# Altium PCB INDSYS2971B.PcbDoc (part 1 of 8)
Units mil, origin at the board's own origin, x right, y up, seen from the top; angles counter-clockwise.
Board outline 6450 x 5820 mil, 6 copper layers (Top Layer, Int1 (PGND), Int2 (AGND), Int3 (Signal), Int4 (PGND), Bottom Layer), stack 70.536 mil thick; 787 components, 431 nets, 2530 pads, 2497 vias.
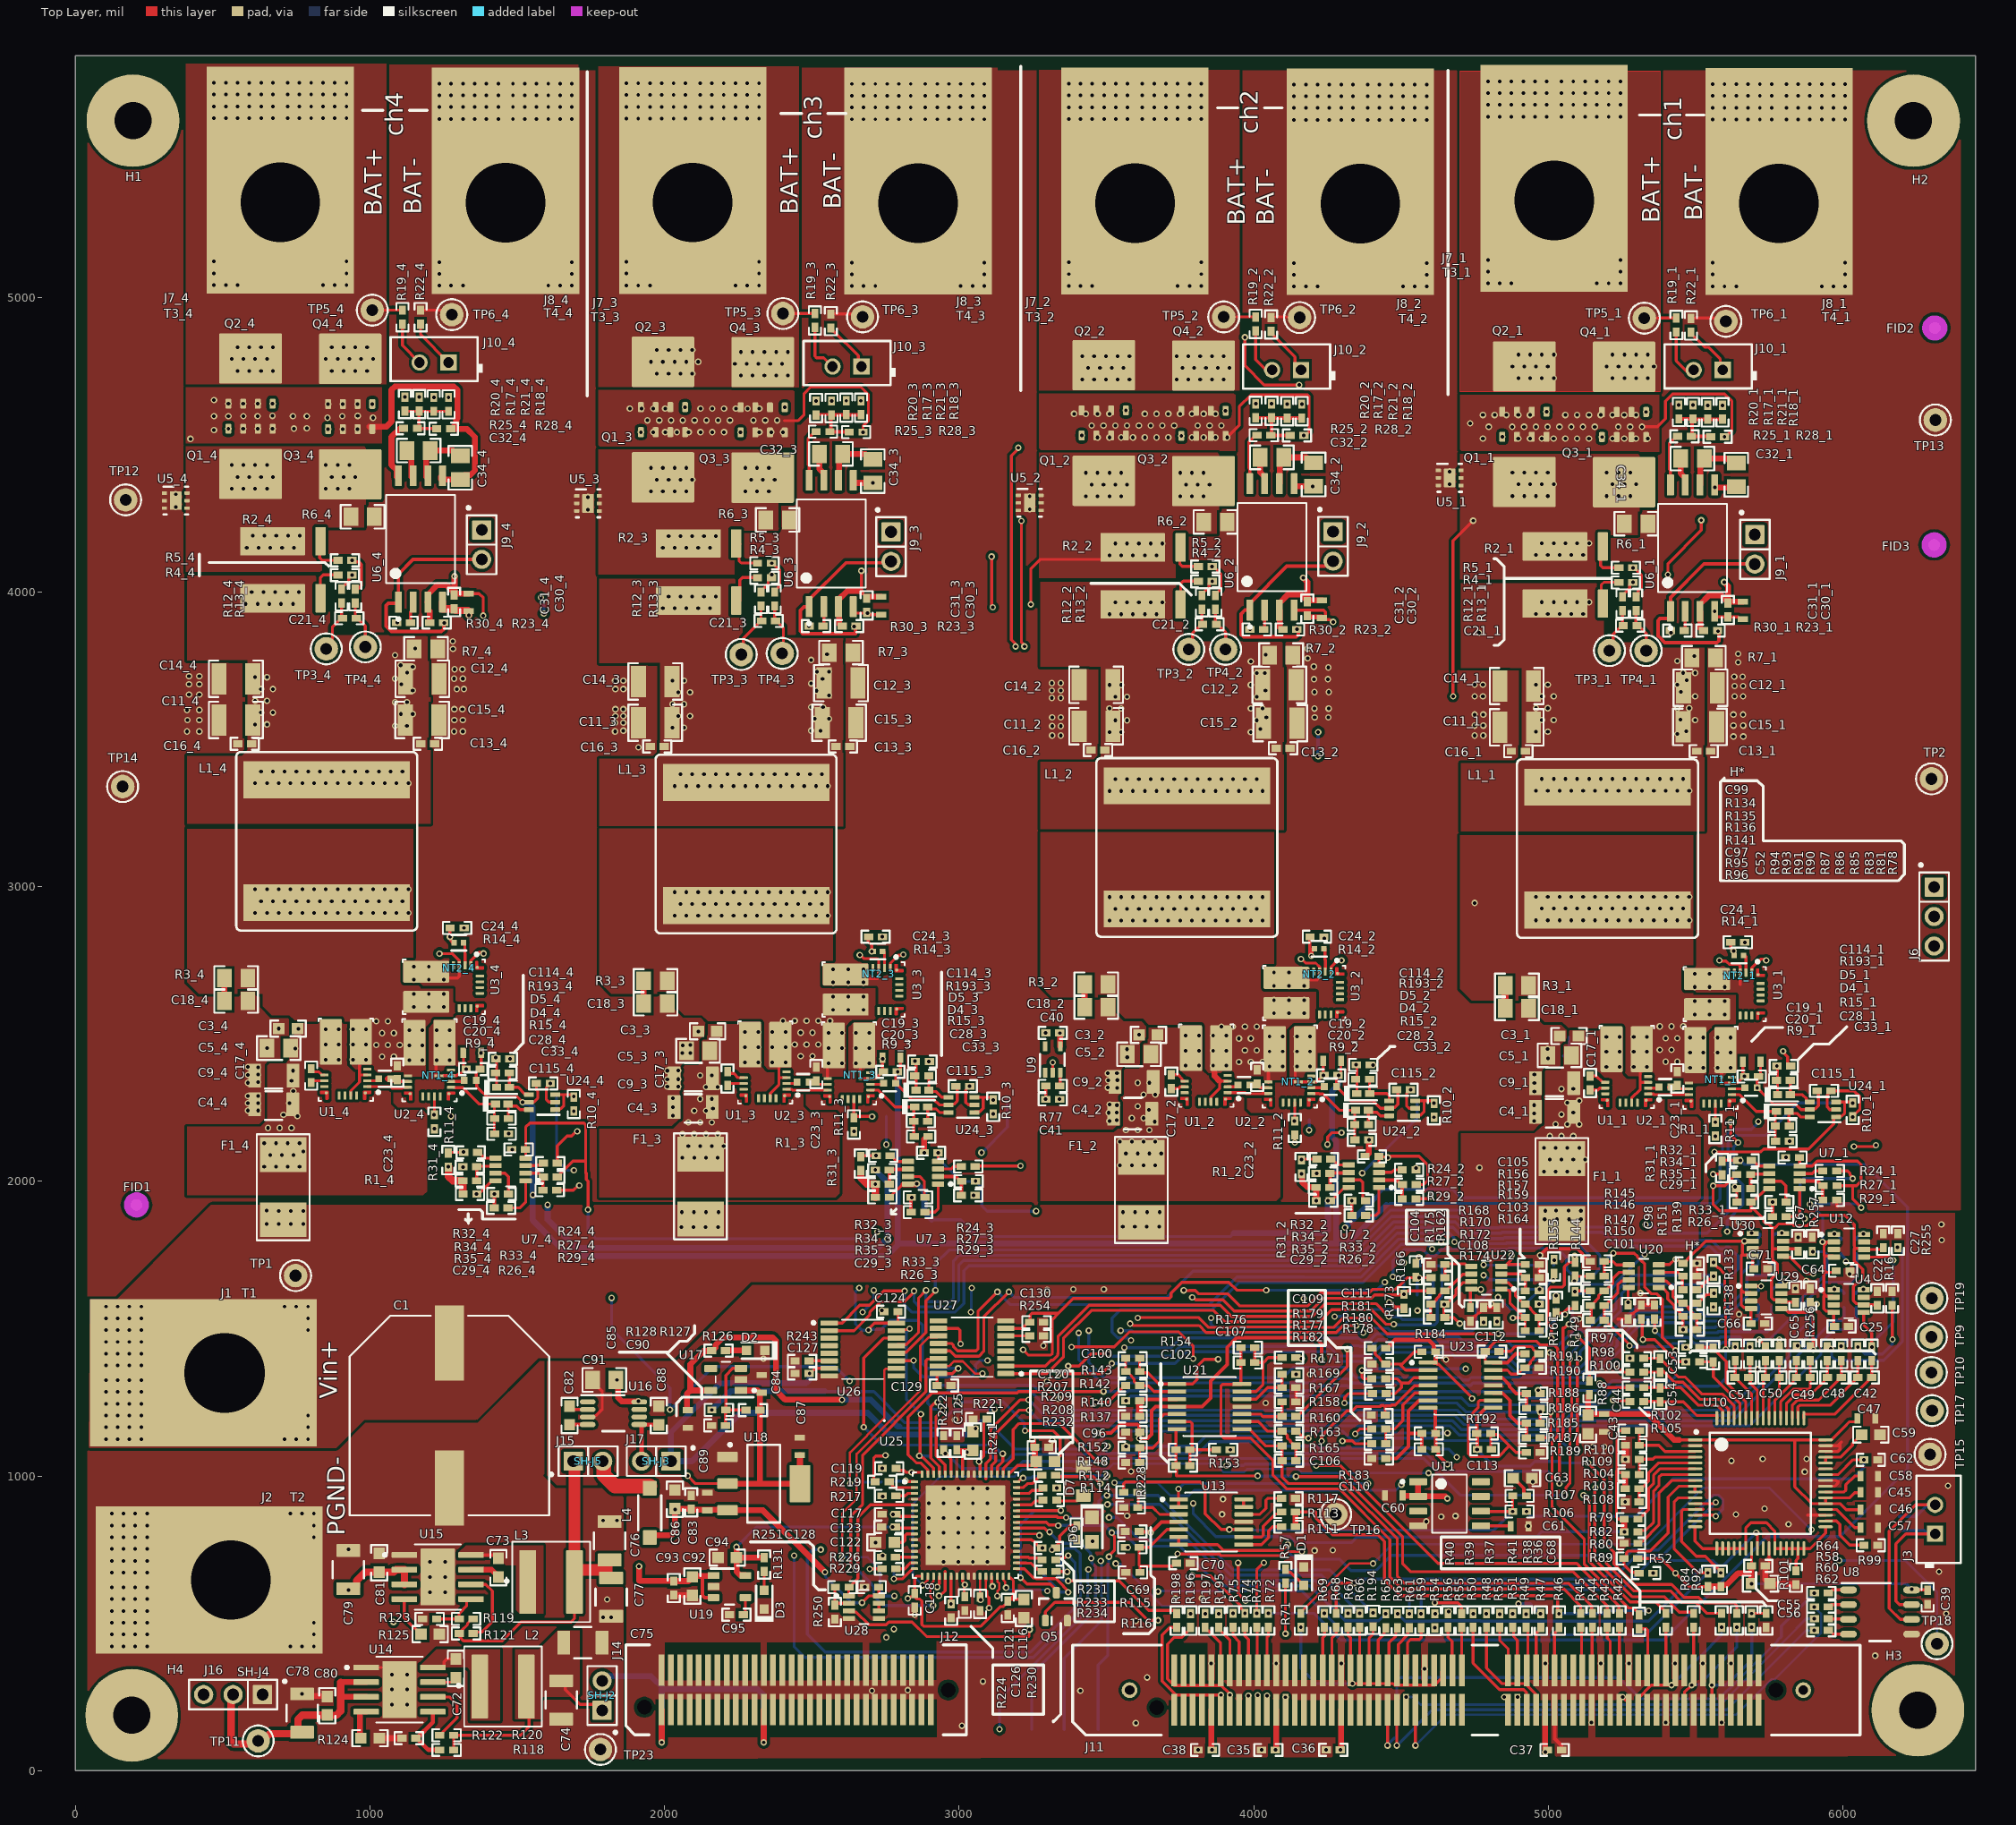
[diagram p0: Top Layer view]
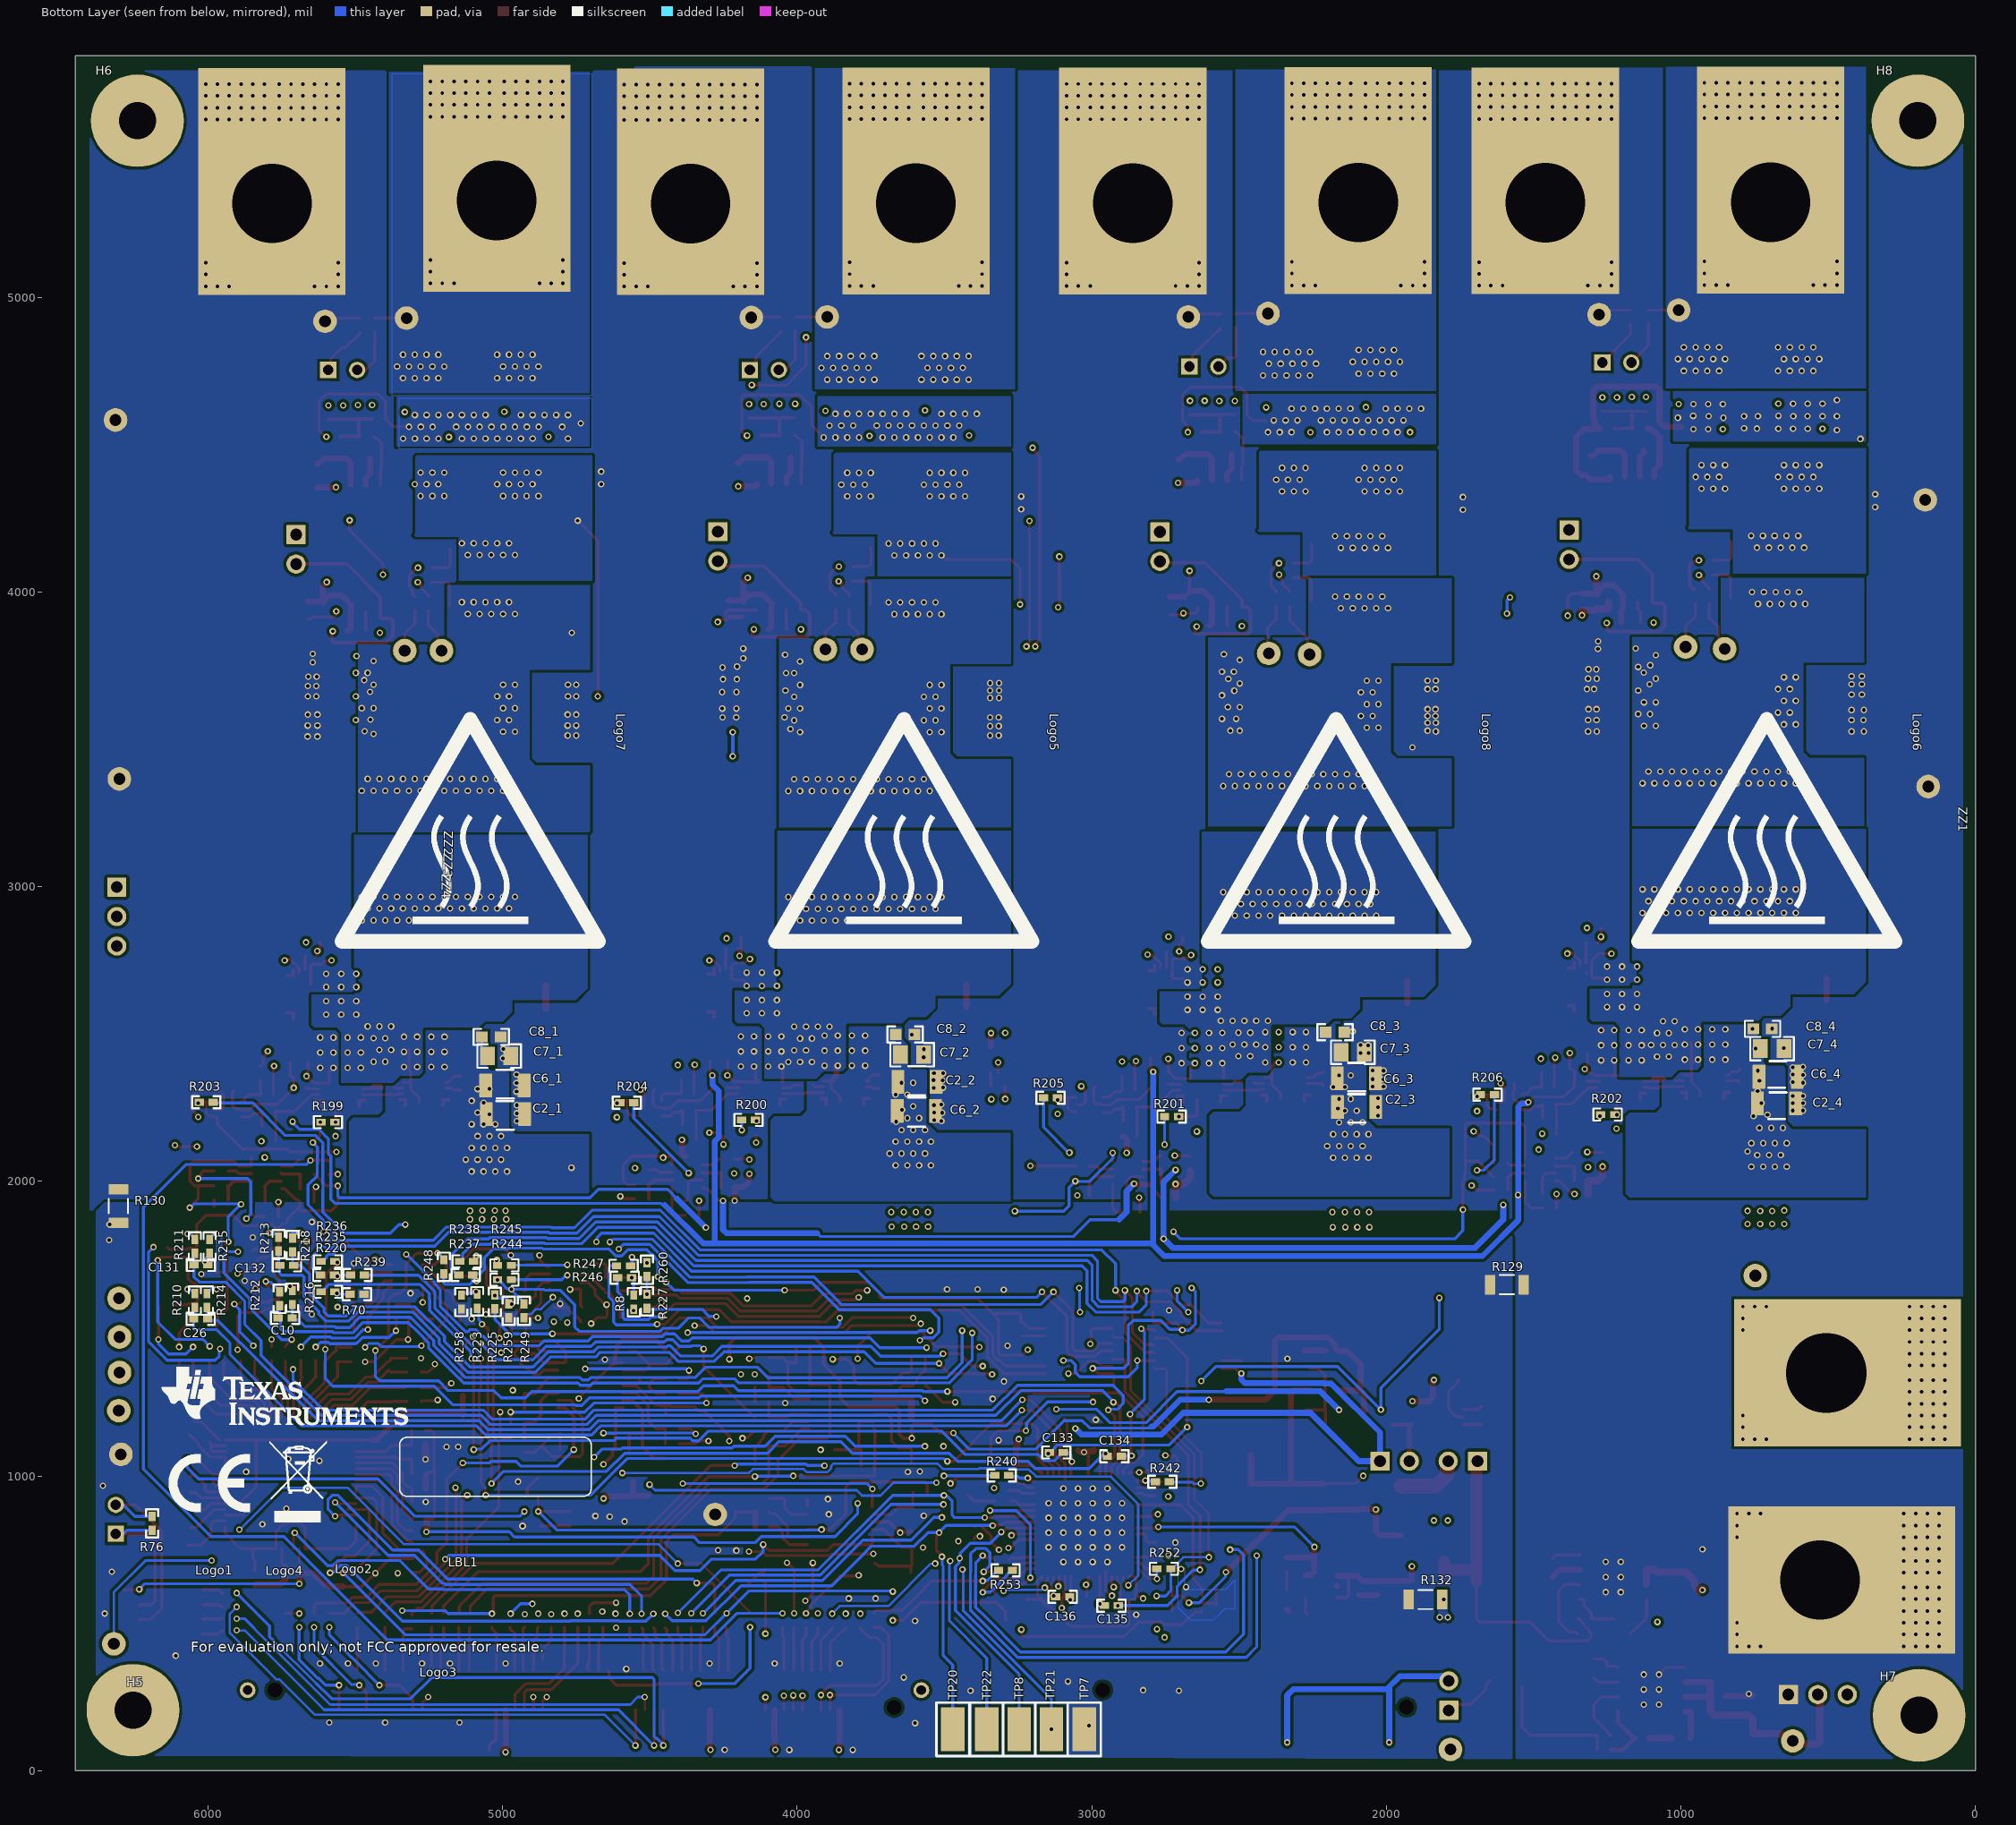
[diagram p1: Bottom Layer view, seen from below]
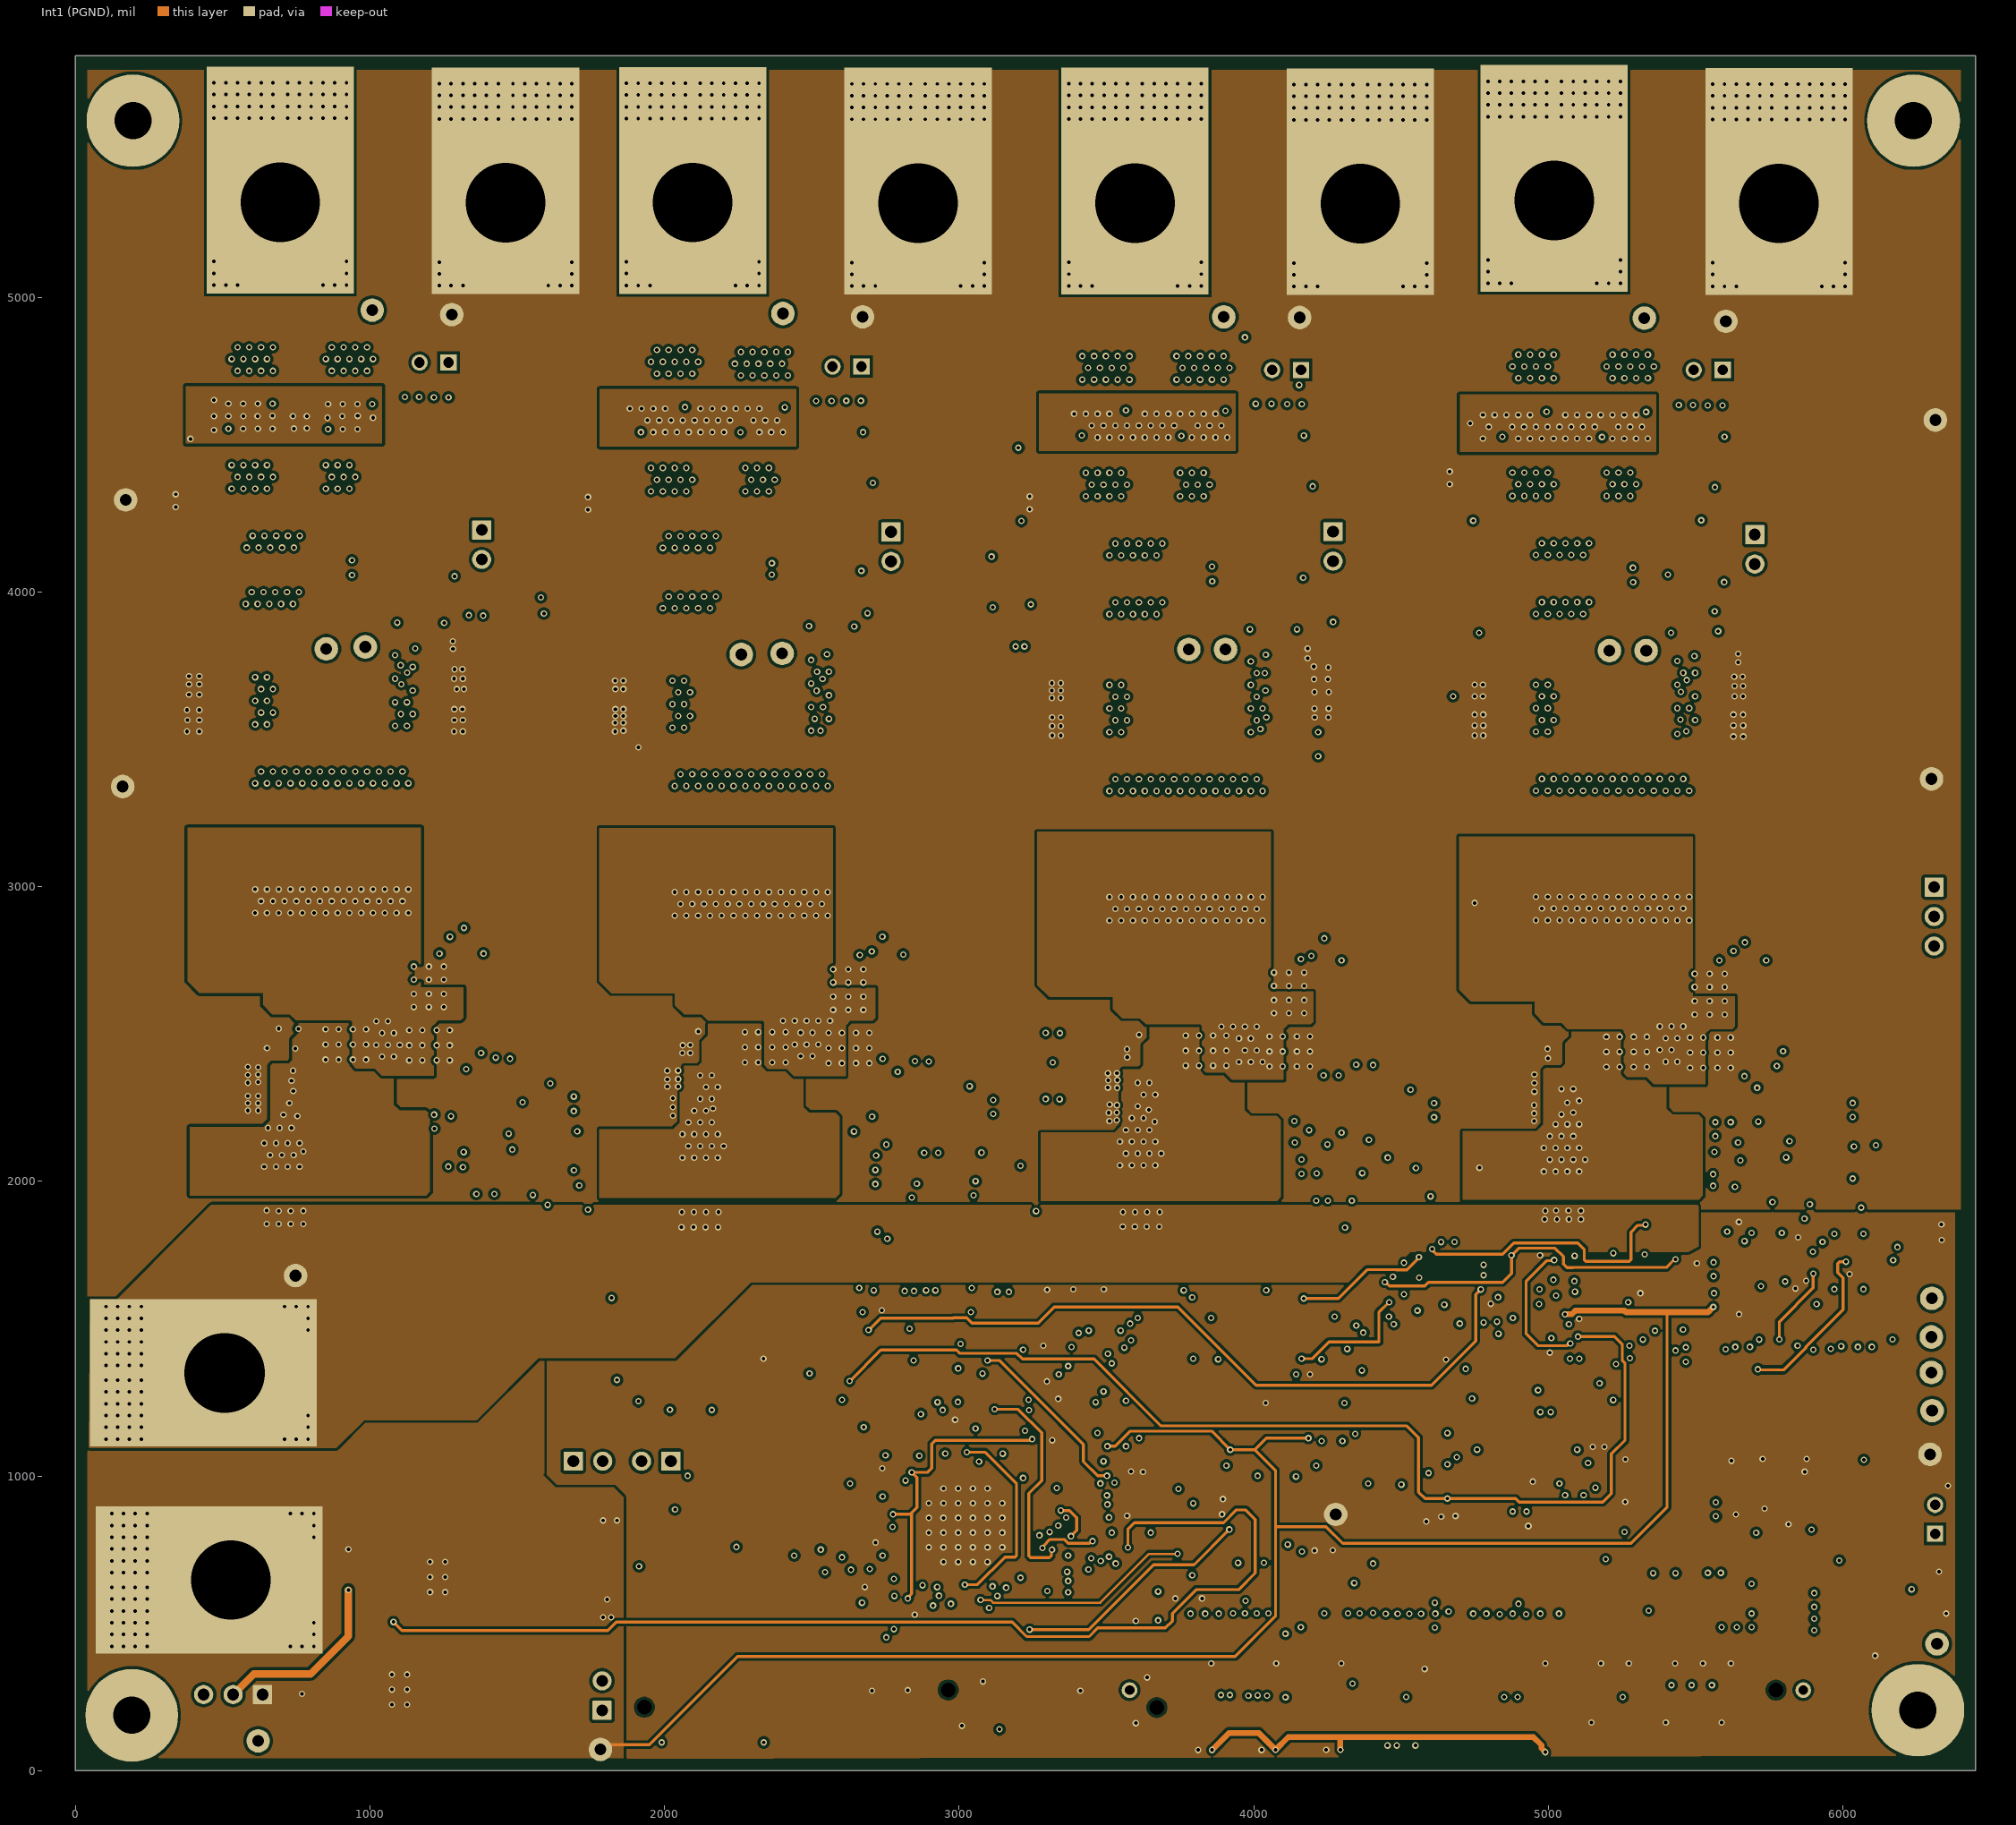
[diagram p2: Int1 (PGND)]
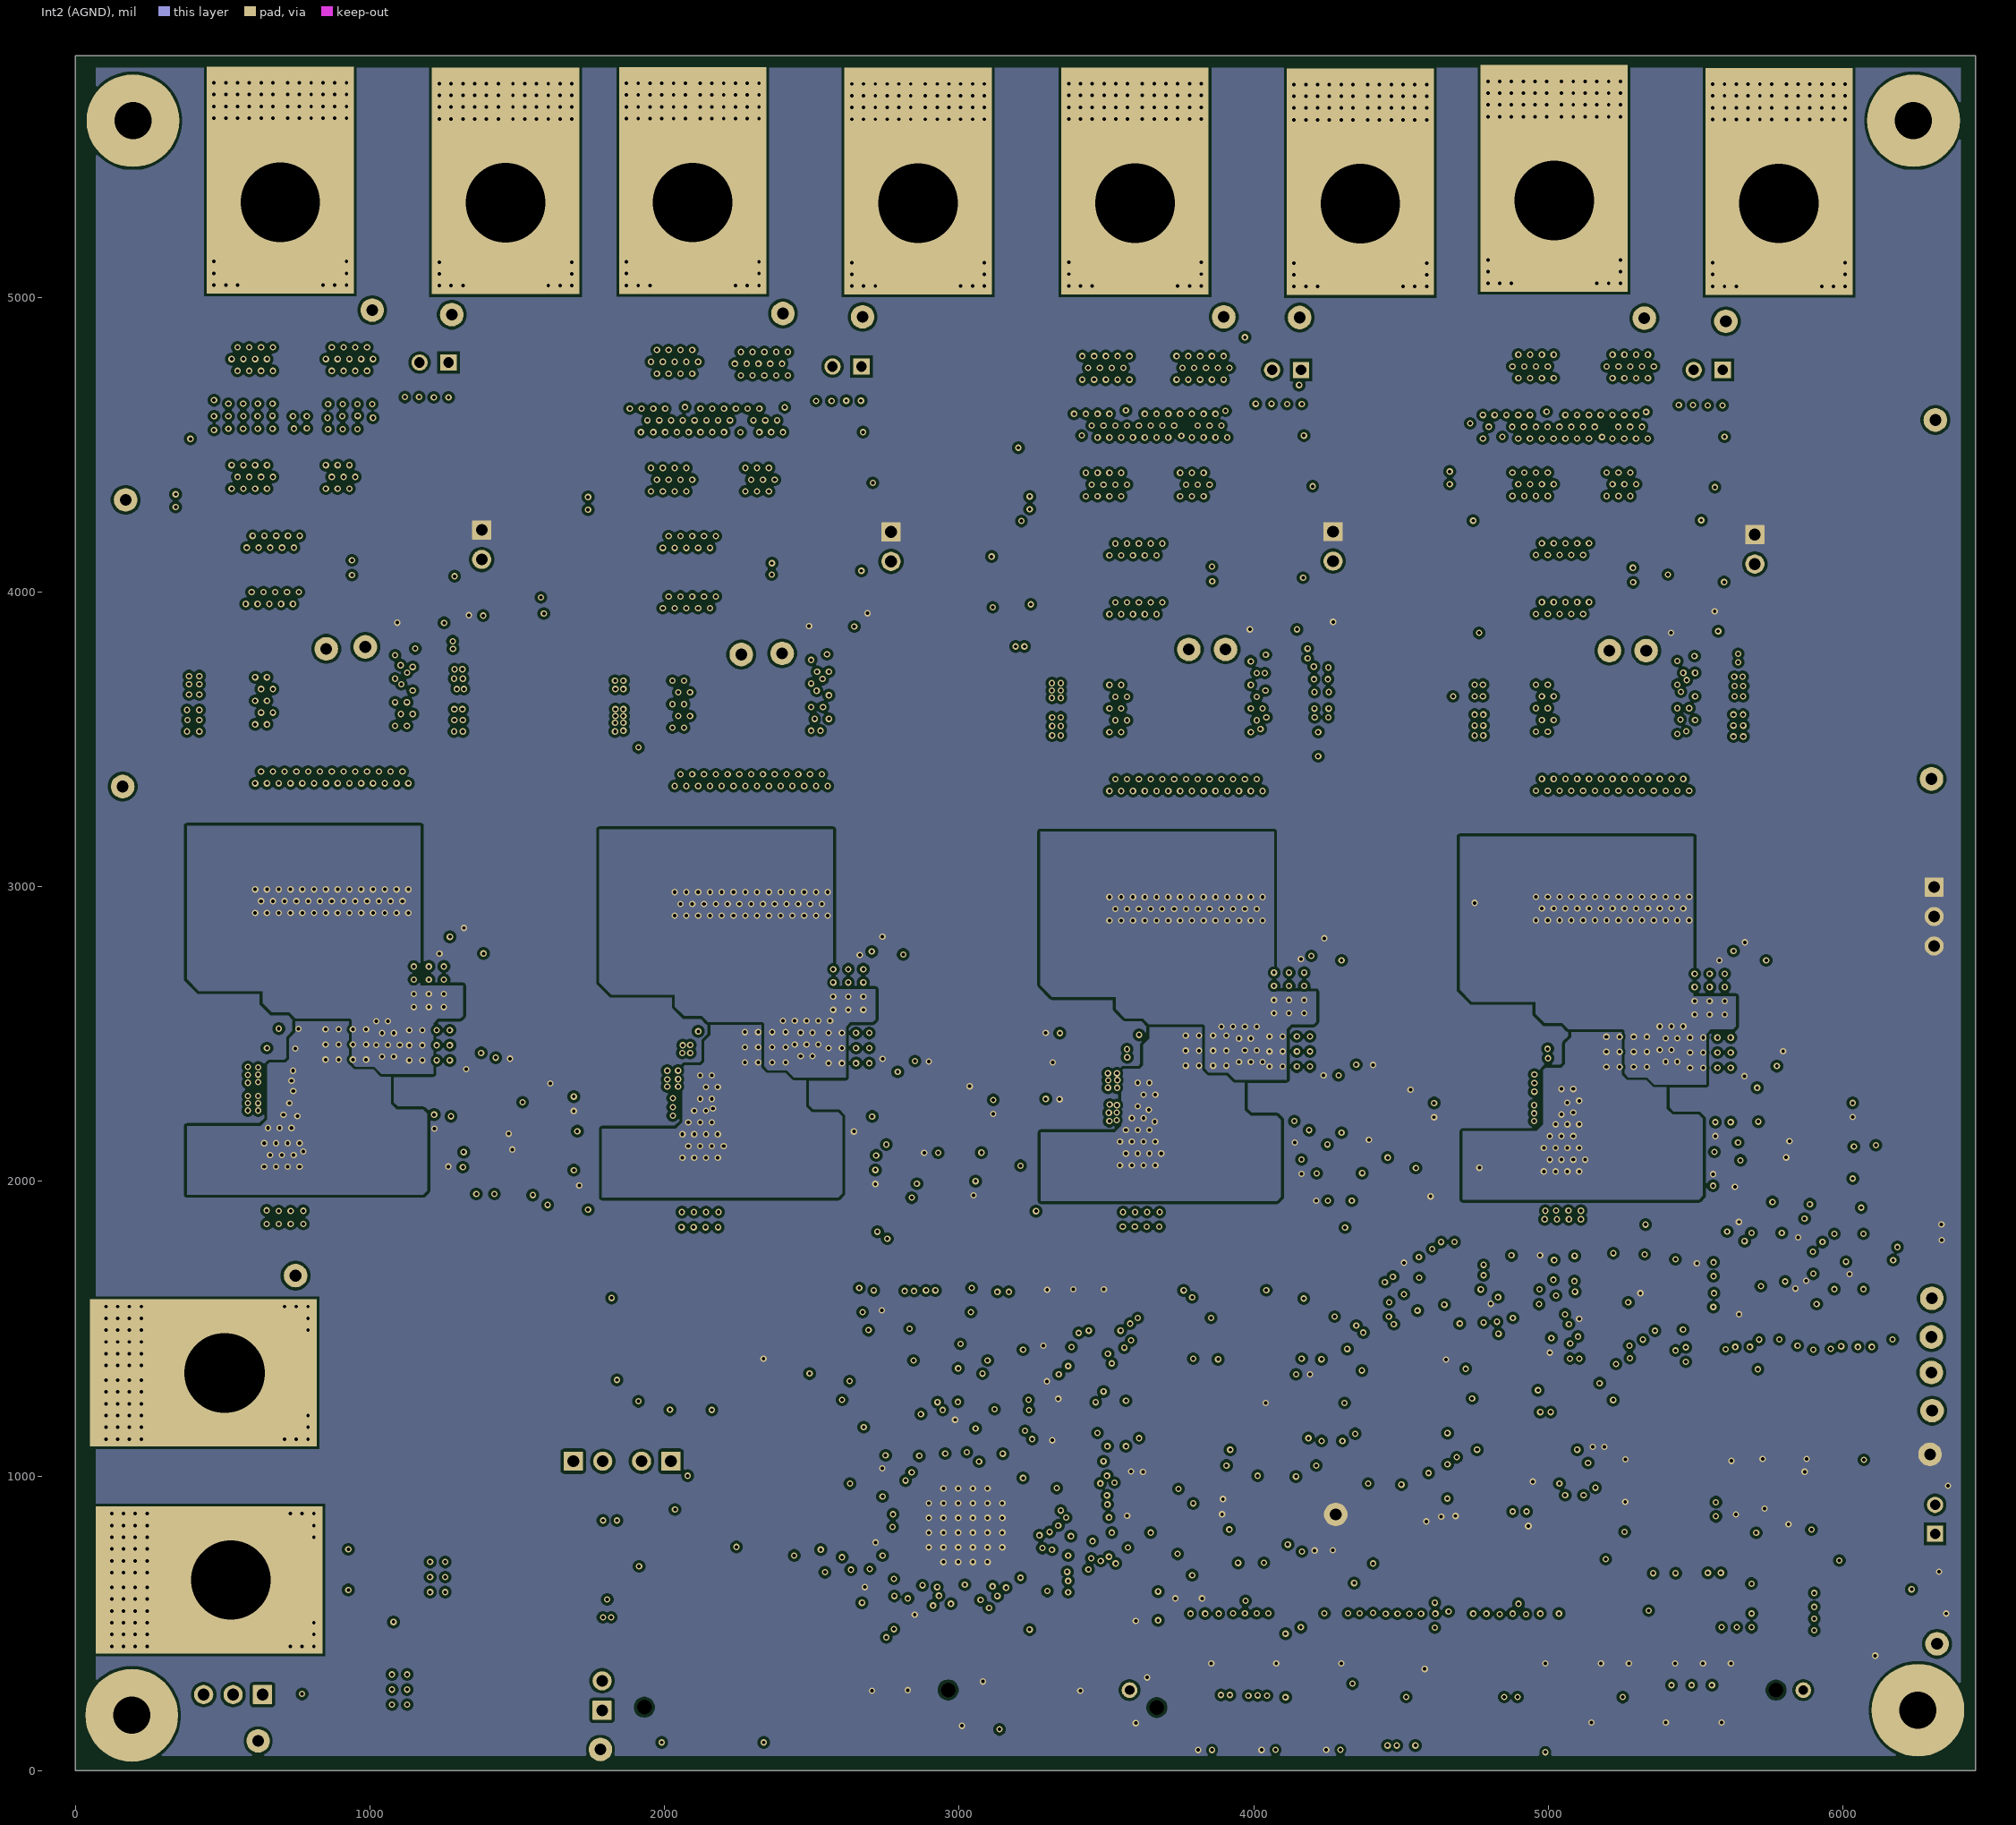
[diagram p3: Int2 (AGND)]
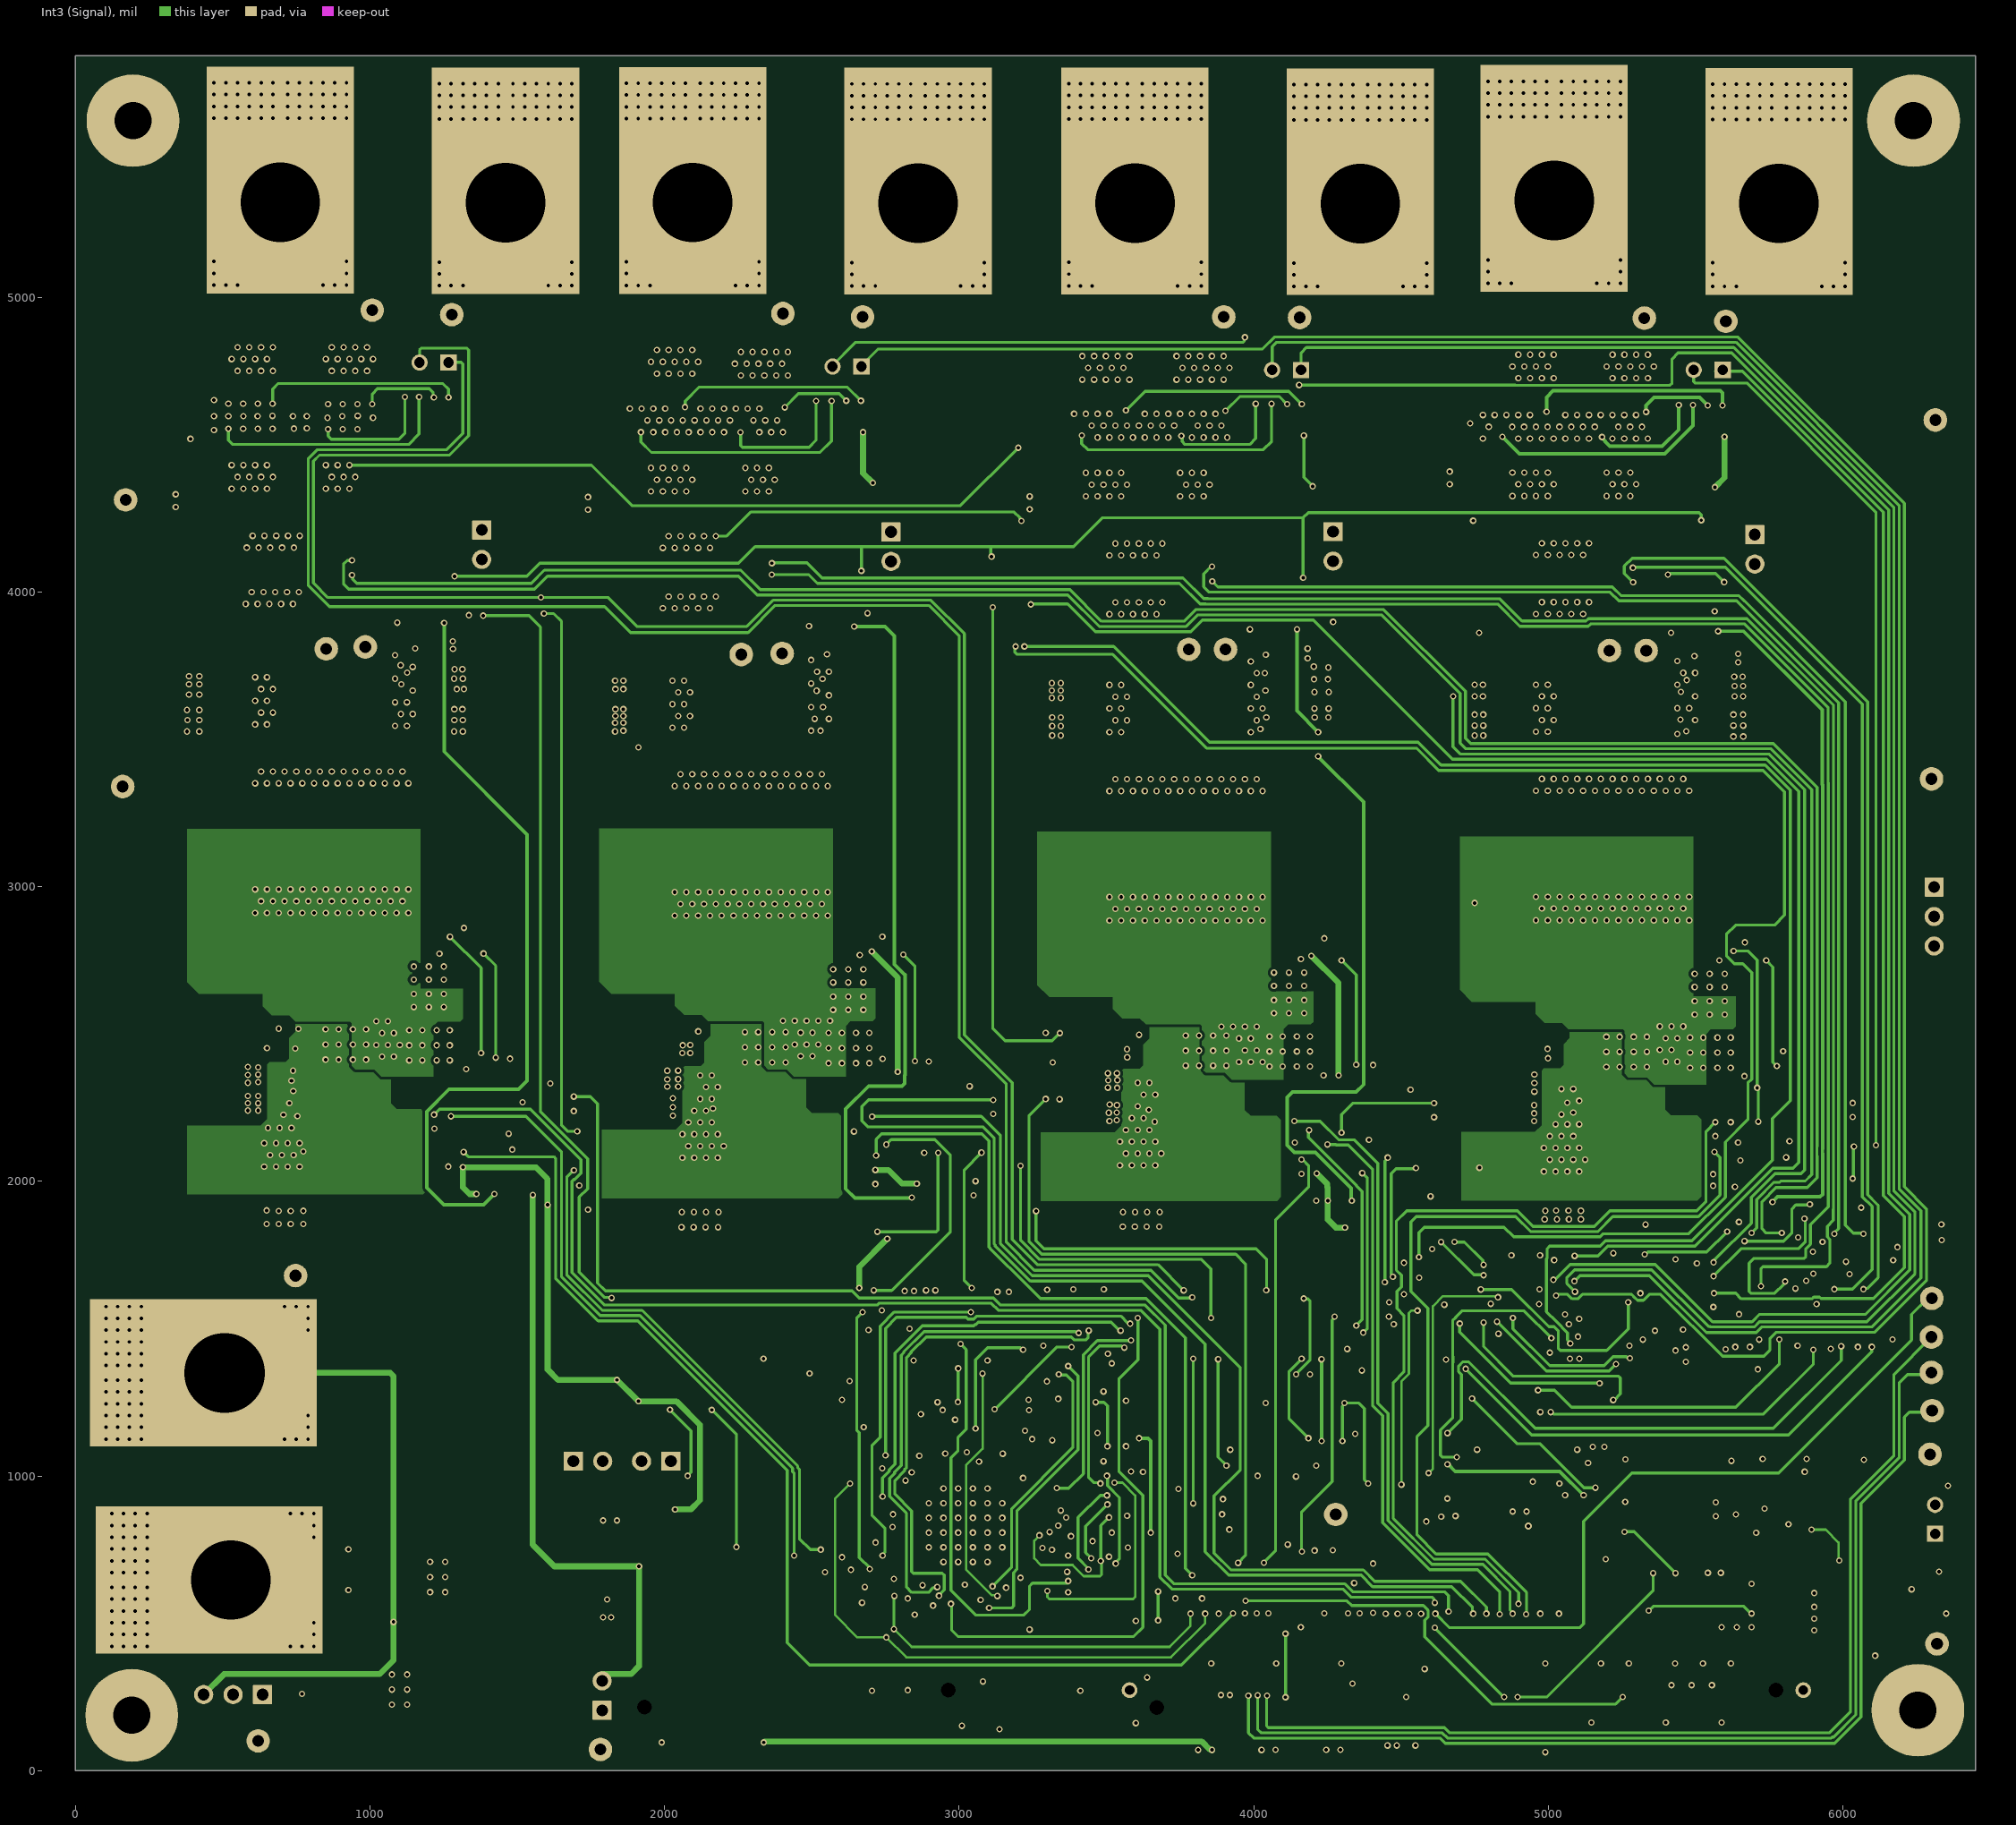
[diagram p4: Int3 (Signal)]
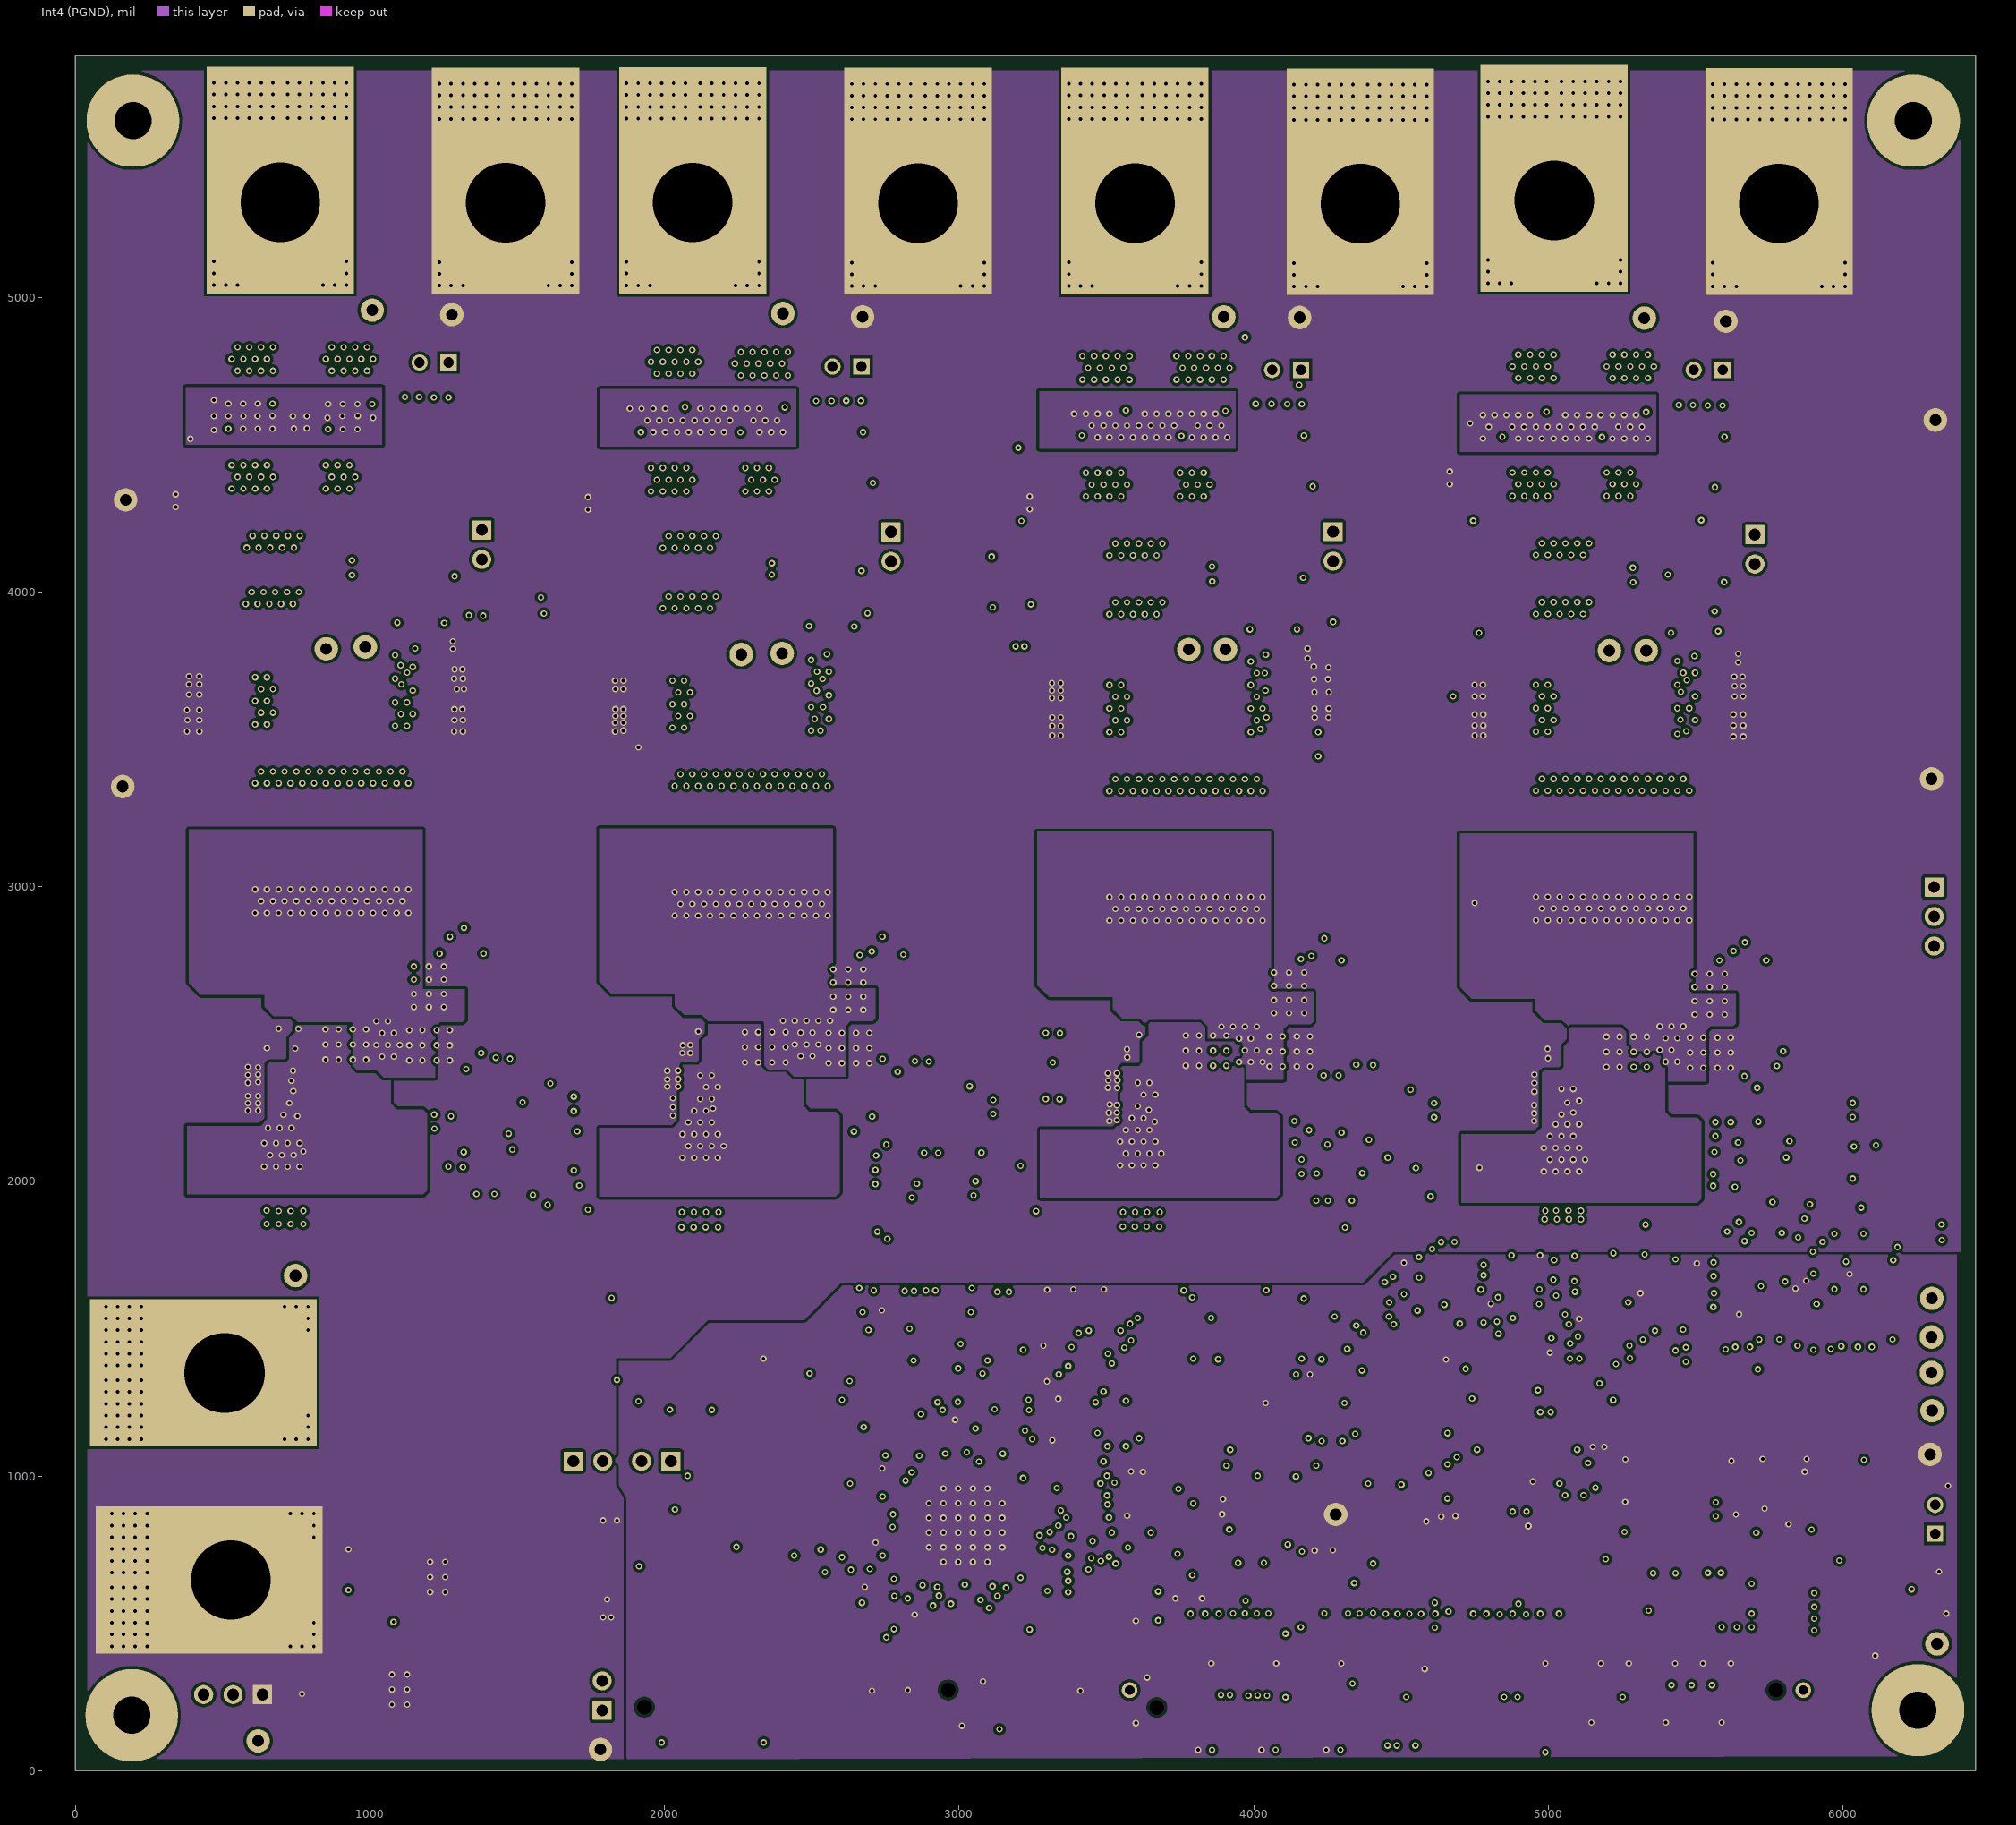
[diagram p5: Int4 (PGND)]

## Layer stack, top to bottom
Top Solder: solder mask 1, SM-001, Dk 4
Top Layer: signal copper 2.756
Dielectric 6: prepreg 2.8, PP-006, Dk 4.1
Dielectric 1: prepreg 5.1, PP-017, Dk 4.3
Int1 (PGND): signal copper 2.756
Dielectric 2: prepreg 5.1, PP-017, Dk 4.3
Int2 (AGND): signal copper 2.756
Dielectric 3: core 28, Core-039, Dk 4.8
Int3 (Signal): signal copper 2.756
Dielectric 4: prepreg 5.1, PP-017, Dk 4.3
Int4 (PGND): signal copper 2.756
Dielectric 5: prepreg 5.1, PP-017, Dk 4.3
Dielectric 7: prepreg 2.8, PP-006, Dk 4.1
Bottom Layer: signal copper 2.756
Bottom Solder: solder mask 1, SM-001, Dk 4

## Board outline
0,0.14 6450,0.14 6450,5820.14 0,5820.14

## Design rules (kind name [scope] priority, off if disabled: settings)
AcuteAngle [All] p1: minimum=4.40000000000000E+0001 checktracksonly=FALSE
AssemblyTestPointUsage [All] p1: valid=2
BoardOutlineClearance BoardOutlineClearance_MountingHoles [OnCopper and InComponentClass('Mounting Holes')] p1: gap=39.37 ignorepadtopadclearanceinfootprint=FALSE
BoardOutlineClearance BoardOutlineClearance_Poly [OnCopper and IsPoly] p2: gap=25 ignorepadtopadclearanceinfootprint=FALSE
BoardOutlineClearance [OnCopper and Not InComponentClass('Logo') and not InComponentClass('FiducialMark') and not InRegion(1000,500,4000,800) and not InPoly] p3: gap=30 ignorepadtopadclearanceinfootprint=FALSE
Clearance Clearance_1 [(InNet('PGND') AND (InComponent('T4') OR InComponent('J4')))] p1: gap=10 ignorepadtopadclearanceinfootprint=FALSE except(0: Arc-Hole Track-Hole SMDPad-Hole THPad-Hole Via-Hole Fill-Hole Poly-Hole Region-Hole Text-Hole)
Clearance Clearance_Keepouts [((IsTrack Or IsArc) And Not InPoly) And IsFree and IsKeepOut vs ((IsTrack Or IsArc) And Not InPoly) And IsFree and IsKeepOut] p2: gap=0 ignorepadtopadclearanceinfootprint=FALSE
Clearance Clearance_Poly [InPolygon] p3: gap=10 ignorepadtopadclearanceinfootprint=TRUE
Clearance Clearance_FiducialMark [IsKeepOut and InComponentClass('FiducialMark') vs IsPad and InComponentClass('FiducialMark')] p4: gap=0 ignorepadtopadclearanceinfootprint=FALSE
Clearance [All] p5: gap=7.87 ignorepadtopadclearanceinfootprint=TRUE
ComponentClearance I/OcomponentClearance [HasFootprint('Johnson_108-0740-001') vs HasFootprint('Panduit_CXS70-14-C')] p1: gap=0 collisioncheckmode=3 verticalgap=0 showdistances=FALSE
ComponentClearance ComponentClearance_MountingHoles_FiducialMarks [InComponentClass('Mounting Holes') vs InComponentClass('FiducialMark')] p2: gap=50 collisioncheckmode=3 verticalgap=10 showdistances=FALSE
ComponentClearance ComponentClearance_Shunt [InComponentClass('Header') vs InComponentClass('Shunt')] p3: gap=0 collisioncheckmode=3 verticalgap=0 showdistances=FALSE
ComponentClearance ComponentClearance_Logo [InComponentClass('Logo')] p4: gap=30 collisioncheckmode=3 verticalgap=10 showdistances=FALSE
ComponentClearance ComponentClearance_ScrewToNut [(HasFootprint('NY PMS 440 0025 PH')) vs (HasFootprint('Keystone_1902C'))] p5: gap=5 collisioncheckmode=3 verticalgap=10 showdistances=FALSE
ComponentClearance ComponentClearance_MountingHoles [InComponentClass('Mounting Holes')] p6: gap=100 collisioncheckmode=3 verticalgap=100000 showdistances=FALSE
ComponentClearance ComponentClearance_SmallPassives [HasFootprint('0201*') or HasFootprint('0402*') or HasFootprint('0508') or HasFootprint('0603*') or HasFootprint('0612') or HasFootprint('0805*') or HasFootprint('0815*') or HasFootprint('0830*') or HasFootprint('1206*') or HasFootprint('1210*') or HasFootprint('1808*') or HasFootprint('1812*') or HasFootprint('1825*') or HasFootprint('2010*') or HasFootprint('2220*') or HasFootprint('2225*') or HasFootprint('2512*') or HasFootprint('2728*') or HasFootprint('3518*') vs HasFootprint('0201*') or HasFootprint('0402*') or HasFootprint('0508') or HasFootprint('0603*') or HasFootprint('0612') or HasFootprint('0805*') or HasFootprint('0815*') or HasFootprint('0830*') or HasFootprint('1206*') or HasFootprint('1210*') or HasFootprint('1808*') or HasFootprint('1812*') or HasFootprint('1825*') or HasFootprint('2010*') or HasFootprint('2220*') or HasFootprint('2225*') or HasFootprint('2512*') or HasFootprint('2728*') or HasFootprint('3518*')] p7: gap=14.96 collisioncheckmode=3 verticalgap=10 showdistances=FALSE
ComponentClearance ComponentClearance_THtoSMT [IsThruComponent vs IsSMTComponent] p8: gap=30 collisioncheckmode=3 verticalgap=30 showdistances=FALSE
ComponentClearance ComponentClearance_THtoTH [IsThruComponent vs IsThruComponent] p9: gap=20 collisioncheckmode=3 verticalgap=30 showdistances=FALSE
ComponentClearance [InComponent('NT1_1','NT1_2','NT1_3','NT1_4','NT2_1','NT2_2','NT2_3','NT2_4','SH-J1','SH-J2','SH-J3','SH-J4','SH-J5')] p10: gap=0 collisioncheckmode=3 verticalgap=0 showdistances=FALSE
DiffPairsRouting [All] p1: maxlimit=100 minlimit=10 mostfreqgap=10 toplayer_minwidth=8 toplayer_maxwidth=15 toplayer_prefwidth=15 midlayer1_minwidth=8 midlayer1_maxwidth=15 midlayer1_prefwidth=15 midlayer2_minwidth=8 midlayer2_maxwidth=15 midlayer2_prefwidth=15 midlayer3_minwidth=15 midlayer3_maxwidth=15 midlayer3_prefwidth=15 midlayer4_minwidth=15 midlayer4_maxwidth=15 midlayer4_prefwidth=15 bottomlayer_minwidth=8 bottomlayer_maxwidth=15 bottomlayer_prefwidth=15 maxuncoupledlength=1000
FabricationTestPointUsage TestPointUsage [All] p1: valid=2 allowmultiple=FALSE
FabricationTestpoint Testpoint [All] p1: side=3 testpointundercomponent=TRUE minsize=40 maxsize=100 preferedsize=60 minholesize=0 maxholesize=40 preferedholesize=32 testpointgrid=1 allowsidetop=TRUE allowsidebottom=TRUE usegrid=TRUE gridtolerance=0.01
FanoutControl Fanout_LCC [IsLCC] p1: bgadir=Out bgaviamode=Centered fanoutstyle=Auto fanoutdirection=Alternating viagrid=1 // Fanout_LCC (Default Rule)
FanoutControl Fanout_BGA [IsBGA] p2: bgadir=Out bgaviamode=Centered fanoutstyle=Auto fanoutdirection=Alternating viagrid=1 // Fanout_BGA (Default Rule)
FanoutControl Fanout_Default [All] p4: bgadir=Out bgaviamode=Centered fanoutstyle=Auto fanoutdirection=Alternating viagrid=1 // Fanout_Default (Default Rule)
FanoutControl Fanout_Small [(CompPinCount < 5)] p5: bgadir=Out bgaviamode=Centered fanoutstyle=Auto fanoutdirection=OutThenIn viagrid=1 // Fanout_Small (Default Rule)
Height [All] p1: minheight=0 maxheight=2000 prefheight=500
HoleSize [All] p1: absolutevalues=TRUE maxlimit=350 minlimit=10 maxpercent=80.000 minpercent=20.000
HoleToHoleClearance I/OHoleClearance [HasFootprint('Johnson_108-0740-001') vs HasFootprint('Panduit_CXS70-14-C')] p1: gap=0 allowstackedmicrovias=TRUE
HoleToHoleClearance [All] p2: gap=10 allowstackedmicrovias=TRUE
MinimumAnnularRing MinimumAnnularRing_ThermalPadVias [IsVia and InAnyComponent] p1: minimumring=4
MinimumAnnularRing [All] p2: minimumring=4
MinimumSolderMaskSliver MinimumSolderMaskSliver_Logo [InComponentClass('Logo') vs InComponentClass('Logo')] p1: minsoldermaskwidth=0.7
MinimumSolderMaskSliver [All] p2: minsoldermaskwidth=0
PlaneConnect [All] p1: planeconnectstyle=Relief reliefexpansion=10 reliefentries=4 reliefconductorwidth=10 reliefairgap=10
PolygonConnect [All] p1: connectstyle=Direct reliefconductorwidth=10 reliefentries=4 polygonreliefangle="90 Angle" airgapwidth=10
RoutingVias [All] p1: holewidth=12.5 width=22 viastyle="Through Hole" minholewidth=12 minwidth=20 maxholewidth=40 maxwidth=65
RoutingVias ThermalPadVias [IsVia and InAnyComponent] p2: holewidth=12 width=22 viastyle="Through Hole" minholewidth=10 minwidth=20 maxholewidth=40 maxwidth=65
SilkToBoardRegionClearance [Not ((IsComment or IsDesignator) And (Hide <> 'False')) and not InRegion(1000,500,4000,800)] p1:
SilkToSilkClearance SilkToSilkClearance_Pb-FreeLogo [(HasFootprint('Pb-Free_Overlay_Medium') OR HasFootprint('Pb-Free_Overlay_Small')) vs (HasFootprint('Pb-Free_Overlay_Medium') OR HasFootprint('Pb-Free_Overlay_Small'))] p1: silktosilkclearance=0
SilkToSilkClearance [All] p2: silktosilkclearance=0
SilkToSolderMaskClearance SilkToComponentPadClearance [All vs IsVia] p1: minsilkscreentomaskgap=0 clearancetoexposedcopper=FALSE
SilkToSolderMaskClearance "Silk to Solder Mask Opening" [Not IsVia vs Not IsVia] p2: minsilkscreentomaskgap=0 clearancetoexposedcopper=FALSE
SolderMaskExpansion [All] p1: expansion=1.97 istentingtop=FALSE
UnRoutedNet [All] p1: checkbadconnections=TRUE
Width [All] p1: maxlimit=100 minlimit=6 preferedwidth=10 checkconnectedcopper=TRUE
12 further rules are at their usual default settings.

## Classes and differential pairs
channel class INDSYS2971B_ReverseBatteryProtection: 1 2 3 4
channel class INDSYS2971B_PowerStage: 1 2 3 4
net class ISENB[1..4]: ISENB1 ISENB2 ISENB3 ISENB4
net class ISENA[1..4]: ISENA1 ISENA2 ISENA3 ISENA4
component class INDSYS2971B_DAC: C10 C26 C116 C117 C118 C119 C120 C121 C122 C123 C124 C125 C126 C127 C128 C129 C130 C131 C132 C133 C134 C135 C136 D6 D7 Q5 R8 R70 R199 R200 R201 R202 R203 R204 R205 R206 R207 R208 R209 R210 R211 R212 R213 R214 R215 R216 R217 R218 R219 R220 R221 R222 R223 R224 R225 R226 R227 R228 R229 R230 R231 R232 R233 R234 R235 R236 R237 R238 R239 R240 R241 R242 R243 R244 R245 R246 R247 R248 R249 R250 R251 R252 R253 R254 R258 R259 R260 TP7 TP8 TP20 TP21 TP22 U25 U26 U27 U28
component class 2: C2_2 C3_2 C4_2 C5_2 C6_2 C7_2 C8_2 C9_2 C11_2 C12_2 C13_2 C14_2 C15_2 C16_2 C17_2 C18_2 C19_2 C20_2 C21_2 C23_2 C24_2 C28_2 C114_2 C115_2 D4_2 D5_2 F1_2 L1_2 NT1_2 NT2_2 R1_2 R2_2 R3_2 R4_2 R5_2 R6_2 R7_2 R9_2 R10_2 R11_2 R12_2 R13_2 R14_2 R15_2 R193_2 TP3_2 TP4_2 U1_2 U2_2 U3_2 U24_2
component class 1: C2_1 C3_1 C4_1 C5_1 C6_1 C7_1 C8_1 C9_1 C11_1 C12_1 C13_1 C14_1 C15_1 C16_1 C17_1 C18_1 C19_1 C20_1 C21_1 C23_1 C24_1 C28_1 C114_1 C115_1 D4_1 D5_1 F1_1 L1_1 NT1_1 NT2_1 R1_1 R2_1 R3_1 R4_1 R5_1 R6_1 R7_1 R9_1 R10_1 R11_1 R12_1 R13_1 R14_1 R15_1 R193_1 TP3_1 TP4_1 U1_1 U2_1 U3_1 U24_1
component class 4: C2_4 C3_4 C4_4 C5_4 C6_4 C7_4 C8_4 C9_4 C11_4 C12_4 C13_4 C14_4 C15_4 C16_4 C17_4 C18_4 C19_4 C20_4 C21_4 C23_4 C24_4 C28_4 C114_4 C115_4 D4_4 D5_4 F1_4 L1_4 NT1_4 NT2_4 R1_4 R2_4 R3_4 R4_4 R5_4 R6_4 R7_4 R9_4 R10_4 R11_4 R12_4 R13_4 R14_4 R15_4 R193_4 TP3_4 TP4_4 U1_4 U2_4 U3_4 U24_4
component class 3: C2_3 C3_3 C4_3 C5_3 C6_3 C7_3 C8_3 C9_3 C11_3 C12_3 C13_3 C14_3 C15_3 C16_3 C17_3 C18_3 C19_3 C20_3 C21_3 C23_3 C24_3 C28_3 C114_3 C115_3 D4_3 D5_3 F1_3 L1_3 NT1_3 NT2_3 R1_3 R2_3 R3_3 R4_3 R5_3 R6_3 R7_3 R9_3 R10_3 R11_3 R12_3 R13_3 R14_3 R15_3 R193_3 TP3_3 TP4_3 U1_3 U2_3 U3_3 U24_3
component class 2: C29_2 C30_2 C31_2 C32_2 C33_2 C34_2 J7_2 J8_2 J9_2 J10_2 Q1_2 Q2_2 Q3_2 Q4_2 R17_2 R18_2 R19_2 R20_2 R21_2 R22_2 R23_2 R24_2 R25_2 R26_2 R27_2 R28_2 R29_2 R30_2 R31_2 R32_2 R33_2 R34_2 R35_2 T3_2 T4_2 TP5_2 TP6_2 U5_2 U6_2 U7_2
component class 1: C29_1 C30_1 C31_1 C32_1 C33_1 C34_1 J7_1 J8_1 J9_1 J10_1 Q1_1 Q2_1 Q3_1 Q4_1 R17_1 R18_1 R19_1 R20_1 R21_1 R22_1 R23_1 R24_1 R25_1 R26_1 R27_1 R28_1 R29_1 R30_1 R31_1 R32_1 R33_1 R34_1 R35_1 T3_1 T4_1 TP5_1 TP6_1 U5_1 U6_1 U7_1
net class VbatP[1..4]: VbatP1 VbatP2 VbatP3 VbatP4
net class VbatN[1..4]: VbatN1 VbatN2 VbatN3 VbatN4
net class PWM_LO[1..4]: PWM_LO1 PWM_LO2 PWM_LO3 PWM_LO4
net class PWM_HO[1..4]: PWM_HO1 PWM_HO2 PWM_HO3 PWM_HO4
net class OUTP[1..4]: OUTP1 OUTP2 OUTP3 OUTP4
net class IoutP[1..4]: IoutP1 IoutP2 IoutP3 IoutP4
net class IoutN[1..4]: IoutN1 IoutN2 IoutN3 IoutN4
net class IOCP[1..4]: IOCP1 IOCP2 IOCP3 IOCP4
net class EN_SSR[1..4]: EN_SSR1 EN_SSR2 EN_SSR3 EN_SSR4
net class BATSP[1..4]: BATSP1 BATSP2 BATSP3 BATSP4
net class BATSN[1..4]: BATSN1 BATSN2 BATSN3 BATSN4
component class INDSYS2971B: C1 J1 J2 J3 J6 T1 T2 TP1 TP2 TP18 TP19 TP23
component class INDSYS2971A_VoltageSense: C96 C97 C98 C99 C100 C101 C102 C103 C104 C105 C106 C107 C108 R133 R134 R135 R136 R137 R138 R139 R140 R141 R142 R143 R144 R145 R146 R147 R148 R149 R150 R151 R152 R153 R154 R155 R156 R157 R158 R159 R160 R161 R162 R163 R164 R165 R166 R167 R168 R169 R170 R171 R172 R173 R174 R175 R176 U20 U21 U22
component class INDSYS2971A_SAR_ADC: C42 C43 C44 C45 C46 C47 C48 C49 C50 C51 C52 C53 C54 C55 C56 C57 C58 C59 C60 C61 C62 C63 C68 C69 C70 R78 R79 R80 R81 R82 R83 R84 R85 R86 R87 R88 R89 R90 R91 R92 R93 R94 R95 R96 R97 R98 R99 R100 R101 R102 R103 R104 R105 R106 R107 R108 R109 R110 R111 R112 R113 R114 R115 R116 R117 U10 U11 U13
component class INDSYS2971A_CurrentSense: C22 C25 C27 C64 C65 C66 C67 C71 C109 C110 C111 C112 C113 R16 R177 R178 R179 R180 R181 R182 R183 R184 R185 R186 R187 R188 R189 R190 R191 R192 R255 R256 R257 U4 U12 U23 U29 U30
component class INDSYS2971A_ControlCard: C35 C36 C37 C38 C39 C40 C41 D1 J11 J12 R36 R37 R38 R39 R40 R41 R42 R43 R44 R45 R46 R47 R48 R49 R50 R51 R52 R53 R54 R55 R56 R57 R58 R59 R60 R61 R62 R63 R64 R65 R66 R67 R68 R69 R71 R72 R73 R74 R75 R76 R77 R194 R195 R196 R197 R198 TP9 TP10 TP17 U8 U9
component class INDSYS2971A_BiasPower: C72 C73 C74 C75 C76 C77 C78 C79 C80 C81 C82 C83 C84 C85 C86 C87 C88 C89 C90 C91 C92 C93 C94 C95 D2 D3 J14 J15 J16 J17 L2 L3 L4 R118 R119 R120 R121 R122 R123 R124 R125 R126 R127 R128 R129 R130 R131 R132 SH-J2 SH-J3 SH-J4 SH-J5 TP11 TP12 TP13 TP14 TP15 TP16 U14 U15 U16 U17 U18 U19
component class INDSYS2971A_Hardware: FID1 FID2 FID3 H1 H2 H3 H4 H5 H6 H7 H8 LBL1 Logo1 Logo2 Logo3 Logo4 Logo5 Logo6 Logo7 Logo8 ZZ1 ZZ2 ZZ3 ZZ4

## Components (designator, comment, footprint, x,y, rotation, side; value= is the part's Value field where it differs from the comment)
C1 "EEV-FK2A151M" SM_RADIAL_J16 1269.43,1205.14 r270 top value=150uF
C2_1 "GRM32EC72A106KE05L" FP-GRM32EC72A106KE05L_1210-MFG 4990.39,2228.51 r0 bottom (schematic designator C2)
C2_2 "GRM32EC72A106KE05L" FP-GRM32EC72A106KE05L_1210-MFG 3593.26,2337.65 r0 bottom (schematic designator C2)
C2_3 "GRM32EC72A106KE05L" FP-GRM32EC72A106KE05L_1210-MFG 2100.59,2252.07 r0 bottom (schematic designator C2)
C2_4 "GRM32EC72A106KE05L" FP-GRM32EC72A106KE05L_1210-MFG 674.73,2264.45 r0 bottom (schematic designator C2)
C3_1 "GRM188R72A104KA35D" 0603 5070.29,2493.43 r180 top value=0.1uF (schematic designator C3)
C3_2 "GRM188R72A104KA35D" 0603 3642.29,2497.43 r180 top value=0.1uF (schematic designator C3)
C3_3 "GRM188R72A104KA35D" 0603 2145.68,2509.04 r180 top value=0.1uF (schematic designator C3)
C3_4 "GRM188R72A104KA35D" 0603 721.67,2518.43 r180 top value=0.1uF (schematic designator C3)
C4_1 "GRM32EC72A106KE05L" FP-GRM32EC72A106KE05L_1210-MFG 5021.26,2236.46 r0 top (schematic designator C4)
C4_2 "GRM32EC72A106KE05L" FP-GRM32EC72A106KE05L_1210-MFG 3589.33,2229.27 r0 top (schematic designator C4)
C4_3 "GRM32EC72A106KE05L" FP-GRM32EC72A106KE05L_1210-MFG 2096.66,2252.07 r0 top (schematic designator C4)
C4_4 "GRM32EC72A106KE05L" FP-GRM32EC72A106KE05L_1210-MFG 672.64,2261.46 r0 top (schematic designator C4)
C5_1 "C2012X7S2A105K125AB" 0805_HV 5038.42,2427.5 r180 top value=1uF (schematic designator C5)
C5_2 "C2012X7S2A105K125AB" 0805_HV 3610.42,2431.5 r180 top value=1uF (schematic designator C5)
C5_3 "C2012X7S2A105K125AB" 0805_HV 2113.81,2443.11 r180 top value=1uF (schematic designator C5)
C5_4 "C2012X7S2A105K125AB" 0805_HV 689.8,2452.5 r180 top value=1uF (schematic designator C5)
C6_1 "GRM32EC72A106KE05L" FP-GRM32EC72A106KE05L_1210-MFG 4992.32,2325.14 r0 bottom (schematic designator C6)
C6_2 "GRM32EC72A106KE05L" FP-GRM32EC72A106KE05L_1210-MFG 3594.96,2239.55 r0 bottom (schematic designator C6)
C6_3 "GRM32EC72A106KE05L" FP-GRM32EC72A106KE05L_1210-MFG 2101.08,2349.18 r0 bottom (schematic designator C6)
C6_4 "GRM32EC72A106KE05L" FP-GRM32EC72A106KE05L_1210-MFG 669.77,2355.13 r0 bottom (schematic designator C6)
C7_1 "C2012X7S2A105K125AB" 0805_HV 5011.9,2425.54 r180 bottom value=1uF (schematic designator C7)
C7_2 "C2012X7S2A105K125AB" 0805_HV 3610,2430 r180 bottom value=1uF (schematic designator C7)
C7_3 "C2012X7S2A105K125AB" 0805_HV 2113.78,2438.21 r180 bottom value=1uF (schematic designator C7)
C7_4 "C2012X7S2A105K125AB" 0805_HV 690.06,2450.63 r180 bottom value=1uF (schematic designator C7)
C8_1 "GRM188R72A104KA35D" 0603 5038.78,2490.47 r180 bottom value=0.1uF (schematic designator C8)
C8_2 "GRM188R72A104KA35D" 0603 3633.61,2499 r180 bottom value=0.1uF (schematic designator C8)
C8_3 "GRM188R72A104KA35D" 0603 2174.17,2506.08 r180 bottom value=0.1uF (schematic designator C8)
C8_4 "GRM188R72A104KA35D" 0603 722.33,2517.74 r180 bottom value=0.1uF (schematic designator C8)
C9_1 "GRM32EC72A106KE05L" FP-GRM32EC72A106KE05L_1210-MFG 5021.75,2333.58 r0 top (schematic designator C9)
C9_2 "GRM32EC72A106KE05L" FP-GRM32EC72A106KE05L_1210-MFG 3593.75,2337.58 r0 top (schematic designator C9)
C9_3 "GRM32EC72A106KE05L" FP-GRM32EC72A106KE05L_1210-MFG 2097.14,2349.18 r0 top (schematic designator C9)
C9_4 "GRM32EC72A106KE05L" FP-GRM32EC72A106KE05L_1210-MFG 673.13,2358.58 r0 top (schematic designator C9)
C10 "GRM155R61C104KA88D" 0402 5738.39,1536.74 r0 bottom value=0.1uF
C11_1 "GRM32EC81C476ME15L" 1210_270 4892.87,3541.11 r180 top value=47uF (schematic designator C11)
C11_2 "GRM32EC81C476ME15L" 1210_270 3464.87,3545.11 r180 top value=47uF (schematic designator C11)
C11_3 "GRM32EC81C476ME15L" 1210_270 1968.26,3556.71 r180 top value=47uF (schematic designator C11)
C11_4 "GRM32EC81C476ME15L" 1210_270 544.24,3566.11 r180 top value=47uF (schematic designator C11)
C12_1 "GRM32EC81C476ME15L" 1210_270 5516.81,3675.52 r0 top value=47uF (schematic designator C12)
C12_2 "GRM32EC81C476ME15L" 1210_270 4087,3685.14 r0 top value=47uF (schematic designator C12)
C12_3 "GRM32EC81C476ME15L" 1210_270 2598.93,3691.13 r0 top value=47uF (schematic designator C12)
C12_4 "GRM32EC81C476ME15L" 1210_270 1177.37,3706.11 r0 top value=47uF (schematic designator C12)
C13_1 "GRM155R61C104KA88D" 0402 5527.48,3460.14 r180 top value=0.1uF (schematic designator C13)
C13_2 "GRM155R61C104KA88D" 0402 4099.48,3470.14 r180 top value=0.1uF (schematic designator C13)
C13_3 "GRM155R61C104KA88D" 0402 2605.5,3476.18 r180 top value=0.1uF (schematic designator C13)
C13_4 "GRM155R61C104KA88D" 0402 1196.09,3485.14 r180 top value=0.1uF (schematic designator C13)
C14_1 "GRM32EC81C476ME15L" 1210_270 4892.87,3681.11 r180 top value=47uF (schematic designator C14)
C14_2 "GRM32EC81C476ME15L" 1210_270 3464.87,3685.11 r180 top value=47uF (schematic designator C14)
C14_3 "GRM32EC81C476ME15L" 1210_270 1968.26,3696.71 r180 top value=47uF (schematic designator C14)
C14_4 "GRM32EC81C476ME15L" 1210_270 544.24,3706.11 r180 top value=47uF (schematic designator C14)
C15_1 "GRM32EC81C476ME15L" 1210_270 5515,3542.53 r0 top value=47uF (schematic designator C15)
C15_2 "GRM32EC81C476ME15L" 1210_270 4090.03,3555.14 r0 top value=47uF (schematic designator C15)
C15_3 "GRM32EC81C476ME15L" 1210_270 2592.2,3556.71 r0 top value=47uF (schematic designator C15)
C15_4 "GRM32EC81C476ME15L" 1210_270 1176.38,3566.11 r0 top value=47uF (schematic designator C15)
C16_1 "GRM155R61C104KA88D" 0402 4898.39,3460.14 r0 top value=0.1uF (schematic designator C16)
C16_2 "GRM155R61C104KA88D" 0402 3471.52,3464.14 r0 top value=0.1uF (schematic designator C16)
C16_3 "GRM155R61C104KA88D" 0402 1974.91,3476.18 r0 top value=0.1uF (schematic designator C16)
C16_4 "GRM155R61C104KA88D" 0402 574.52,3485.14 r0 top value=0.1uF (schematic designator C16)
C17_1 "GRM155R61C104KA88D" 0402 5141.79,2334.17 r270 top value=0.1uF (schematic designator C17)
C17_2 "GRM155R61C104KA88D" 0402 3720.27,2338.48 r270 top value=0.1uF (schematic designator C17)
C17_3 "GRM155R61C104KA88D" 0402 2213.78,2349.18 r270 top value=0.1uF (schematic designator C17)
C17_4 "GRM155R61C104KA88D" 0402 800,2358.96 r270 top value=0.1uF (schematic designator C17)
C18_1 "GRM2165C2A101JA01D" 0805_HV 4893.62,2587.64 r0 top value=100pF (schematic designator C18)
C18_2 "GRM2165C2A101JA01D" 0805_HV 3465.62,2591.64 r0 top value=100pF (schematic designator C18)
C18_3 "GRM2165C2A101JA01D" 0805_HV 1969.01,2603.25 r0 top value=100pF (schematic designator C18)
C18_4 "GRM2165C2A101JA01D" 0805_HV 545,2612.64 r0 top value=100pF (schematic designator C18)
C19_1 "CGA3E1X7R1E105K080AC" 0603S 5690.65,2406.14 r180 top value=1uF (schematic designator C19)
C19_2 "CGA3E1X7R1E105K080AC" 0603S 4266.12,2408.88 r180 top value=1uF (schematic designator C19)
C19_3 "CGA3E1X7R1E105K080AC" 0603S 2770.26,2419.93 r180 top value=1uF (schematic designator C19)
C19_4 "CGA3E1X7R1E105K080AC" 0603S 1347,2436.01 r180 top value=1uF (schematic designator C19)
C20_1 "GRM155R61C104KA88D" 0402 5690.77,2355.98 r0 top value=0.1uF (schematic designator C20)
C20_2 "GRM155R61C104KA88D" 0402 4262.77,2359.98 r0 top value=0.1uF (schematic designator C20)
C20_3 "GRM155R61C104KA88D" 0402 2766.16,2371.59 r0 top value=0.1uF (schematic designator C20)
C20_4 "GRM155R61C104KA88D" 0402 1349.77,2380.98 r0 top value=0.1uF (schematic designator C20)
C21_1 "GRM155R61C104KA88D" 0402 5278,3886.6 r180 top value=0.1uF (schematic designator C21)
C21_2 "GRM155R61C104KA88D" 0402 3850,3890.6 r180 top value=0.1uF (schematic designator C21)
C21_3 "GRM155R61C104KA88D" 0402 2353.39,3902.21 r180 top value=0.1uF (schematic designator C21)
C21_4 "GRM155R61C104KA88D" 0402 929.38,3911.6 r180 top value=0.1uF (schematic designator C21)
C22 "GRM155R61C104KA88D" 0402 6117.06,1602.65 r90 top value=0.1uF
C23_1 "GRM155R61C104KA88D" 0402 5438.39,2349.41 r270 top value=0.1uF (schematic designator C23)
C23_2 "GRM155R61C104KA88D" 0402 4011.63,2354.66 r270 top value=0.1uF (schematic designator C23)
C23_3 "GRM155R61C104KA88D" 0402 2514.88,2363.97 r270 top value=0.1uF (schematic designator C23)
C23_4 "GRM155R61C104KA88D" 0402 1092.08,2368.92 r270 top value=0.1uF (schematic designator C23)
C24_1 "GRM155R61C104KA88D" 0402 5643.56,2811.46 r180 top value=0.1uF (schematic designator C24)
C24_2 "GRM155R61C104KA88D" 0402 4214.59,2830.14 r180 top value=0.1uF (schematic designator C24)
C24_3 "GRM155R61C104KA88D" 0402 2716,2830.14 r180 top value=0.1uF (schematic designator C24)
C24_4 "GRM155R61C104KA88D" 0402 1295.33,2860.14 r180 top value=0.1uF (schematic designator C24)
C25 "GRM155R61C104KA88D" 0402 5995.69,1507.65 r180 top value=0.1uF
C26 "GRM155R61C104KA88D" 0402 6025.31,1533.16 r0 bottom value=0.1uF
C27 "GRM155R61C104KA88D" 0402 6137.31,1798.69 r90 top value=0.1uF
C28_1 "GRM155R72A471KA01D" 0402 5795.37,2136.71 r0 top value=470pF (schematic designator C28)
C28_2 "GRM155R72A471KA01D" 0402 4367.37,2140.71 r0 top value=470pF (schematic designator C28)
C28_3 "GRM155R72A471KA01D" 0402 2870.76,2152.32 r0 top value=470pF (schematic designator C28)
C28_4 "GRM155R72A471KA01D" 0402 1446.75,2161.71 r0 top value=470pF (schematic designator C28)
C29_1 "GRM155R61C104KA88D" 0402 5664.13,1930.14 r180 top value=0.1uF (schematic designator C29)
C29_2 "GRM155R61C104KA88D" 0402 4236.13,1934.14 r180 top value=0.1uF (schematic designator C29)
C29_3 "GRM155R61C104KA88D" 0402 2739.52,1945.75 r180 top value=0.1uF (schematic designator C29)
C29_4 "GRM155R61C104KA88D" 0402 1339.13,1957.08 r180 top value=0.1uF (schematic designator C29)
C30_1 "CGA3E1X7R1E105K080AC" 0603S 5660,3938.09 r90 top value=1uF (schematic designator C30)
C30_2 "CGA3E1X7R1E105K080AC" 0603S 4232,3942.09 r90 top value=1uF (schematic designator C30)
C30_3 "CGA3E1X7R1E105K080AC" 0603S 2735.39,3953.7 r90 top value=1uF (schematic designator C30)
C30_4 "CGA3E1X7R1E105K080AC" 0603S 1335,3965.03 r90 top value=1uF (schematic designator C30)
C31_1 "GRM155R61C104KA88D" 0402 5610,3939.5 r90 top value=0.1uF (schematic designator C31)
C31_2 "GRM155R61C104KA88D" 0402 4182,3943.5 r90 top value=0.1uF (schematic designator C31)
C31_3 "GRM155R61C104KA88D" 0402 2685.39,3955.11 r90 top value=0.1uF (schematic designator C31)
C31_4 "GRM155R61C104KA88D" 0402 1285,3966.44 r90 top value=0.1uF (schematic designator C31)
C32_1 "GRM21BR61H475KE51L" 0805_HV 5489.57,4453.49 r0 top value=4.7uF (schematic designator C32)
C32_2 "GRM21BR61H475KE51L" 0805_HV 4061.57,4457.49 r0 top value=4.7uF (schematic designator C32)
C32_3 "GRM21BR61H475KE51L" 0805_HV 2564.97,4469.1 r0 top value=4.7uF (schematic designator C32)
C32_4 "GRM21BR61H475KE51L" 0805_HV 1164.57,4480.43 r0 top value=4.7uF (schematic designator C32)
C33_1 "GRM155R61C104KA88D" 0402 5829.37,2081.14 r180 top value=0.1uF (schematic designator C33)
C33_2 "GRM155R61C104KA88D" 0402 4401.37,2085.14 r180 top value=0.1uF (schematic designator C33)
C33_3 "GRM155R61C104KA88D" 0402 2904.77,2096.75 r180 top value=0.1uF (schematic designator C33)
C33_4 "GRM155R61C104KA88D" 0402 1504.37,2108.08 r180 top value=0.1uF (schematic designator C33)
C34_1 "GRM21BR61H475KE51L" 0805_HV 5638.43,4398.46 r270 top value=4.7uF (schematic designator C34)
C34_2 "GRM21BR61H475KE51L" 0805_HV 4203.3,4399.17 r270 top value=4.7uF (schematic designator C34)
C34_3 "GRM21BR61H475KE51L" 0805_HV 2706.69,4410.78 r270 top value=4.7uF (schematic designator C34)
C34_4 "GRM21BR61H475KE51L" 0805_HV 1306.3,4422.11 r270 top value=4.7uF (schematic designator C34)
C35 "GRM155R61C104KA88D" 0402 4050,70.14 r0 top value=0.1uF
C36 "GRM155R61C104KA88D" 0402 4270,70.64 r0 top value=0.1uF
C37 "GRM155R61C104KA88D" 0402 5021.34,70.14 r180 top value=0.1uF
C38 "GRM155R61C104KA88D" 0402 3835,70.14 r0 top value=0.1uF
C39 "GRM155R61C104KA88D" 0402 6288,588.02 r90 top value=0.1uF
C40 "GRM155R61C104KA88D" 0402 3317.5,2503.72 r0 top value=0.1uF
C41 "GRM155R71C153KA01D" 0402 3317.5,2278.72 r0 top value=0.015uF
C42 "GRM155R61E472KA01D" 0402 6074.65,1334.56 r180 top value=4700pF
C43 "GRM188R61E106MA73D" 0603 5135,1175.14 r270 top value=10uF
C44 "CGA3E1X7R1E105K080AC" 0603S 5190,1180.14 r270 top value=1uF
C45 "CGA3E1X7R1E105K080AC" 0603S 6090,945.14 r0 top value=1uF
C46 "CGA3E1X7R1E105K080AC" 0603S 6090,885.14 r0 top value=1uF
C47 "CGA3E1X7R1E105K080AC" 0603S 6080,1195.14 r0 top value=1uF
C48 "GRM155R61E472KA01D" 0402 5971.02,1334.56 r180 top value=4700pF
C49 "GRM155R61E472KA01D" 0402 5865.67,1334.56 r180 top value=4700pF
C50 "GRM155R61E472KA01D" 0402 5761.02,1334.56 r180 top value=4700pF
C51 "GRM155R61E472KA01D" 0402 5656.58,1334.56 r180 top value=4700pF
C52 "GRM155R61E472KA01D" 0402 5560,1410.14 r270 top value=4700pF
C53 "GRM155R61E472KA01D" 0402 5380,1375.14 r270 top value=4700pF
C54 "GRM155R61E472KA01D" 0402 5380,1275.14 r270 top value=4700pF
C55 "GRM155R61C104KA88D" 0402 5713.15,694.56 r0 top value=0.1uF
C56 "GRM188R61E106MA73D" 0603 5721.02,634.48 r0 top value=10uF
C57 "CGA3E1X7R1E105K080AC" 0603S 6090,825.14 r0 top value=1uF
C58 "CGA3E1X7R1E105K080AC" 0603S 6090,1000.14 r0 top value=1uF
C59 "GRM188R61E106MA73D" 0603 6095,1140.14 r0 top value=10uF
C60 "CGA3E1X7R1E105K080AC" 0603S 4475.55,934.59 r180 top value=1uF
C61 "CGA3E1X7R1E105K080AC" 0603S 4902.71,829.49 r0 top value=1uF
C62 "GRM155R61C104KA88D" 0402 6095,1055.14 r0 top value=0.1uF
C63 "GRM188R61E106MA73D" 0603 4912.71,992.76 r0 top value=10uF
C64 "GRM155R61C104KA88D" 0402 6000.93,1696.57 r180 top value=0.1uF
C65 "GRM155R61C104KA88D" 0402 5839.5,1612.46 r90 top value=0.1uF
C66 "GRM155R61C104KA88D" 0402 5711.75,1517.46 r180 top value=0.1uF
C67 "GRM155R61C104KA88D" 0402 5848.1,1786.56 r90 top value=0.1uF
C68 "GRM155R72A471KA01D" 0402 5740,510.14 r90 top value=470pF
C69 "GRM155R61C104KA88D" 0402 3587.44,812.17 r180 top value=0.1uF
C70 "GRM155R71C153KA01D" 0402 3761.61,704.02 r0 top value=0.015uF
C71 "GRM155R61C104KA88D" 0402 5721.45,1703.3 r180 top value=0.1uF
C72 "GRM188R72A104KA35D" 0603 1291.38,347.24 r90 top value=0.1uF
C73 "GRM188R72A104KA35D" 0603 1435.75,688.96 r90 top value=0.1uF
C74 "GRM32EC72A106KE05L" FP-GRM32EC72A106KE05L_1210-MFG 1648.47,239.91 r90 top
C75 "GRM32EC72A106KE05L" FP-GRM32EC72A106KE05L_1210-MFG 1722.54,434.63 r180 top
C76 "GRM32EC72A106KE05L" FP-GRM32EC72A106KE05L_1210-MFG 1813.19,780.11 r270 top
C77 "GRM32EC72A106KE05L" FP-GRM32EC72A106KE05L_1210-MFG 1818.39,588.92 r90 top
C78 "GRM32EC72A106KE05L" FP-GRM32EC72A106KE05L_1210-MFG 769.1,195.18 r270 top
C79 "GRM32EC72A106KE05L" FP-GRM32EC72A106KE05L_1210-MFG 926.34,682.07 r270 top
C80 "GRM188R72A104KA35D" 0603 854.7,220.14 r90 top value=0.1uF
C81 "GRM188R72A104KA35D" 0603 1030.87,705.25 r90 top value=0.1uF
C82 "GRM188R61E106MA73D" 0603 1677.17,1205.64 r90 top value=10uF
C83 "GRM155R61C104KA88D" 0402 2090,910.88 r270 top value=0.1uF
C84 "CGA3E1X7R1E105K080AC" 0603S 2330.17,1312.77 r90 top value=1uF
C85 "CGA3E1X7R1E105K080AC" 0603S 2078.25,1193.45 r270 top value=1uF
C86 "GRM188R61E106MA73D" 0603 2035,920.88 r90 top value=10uF
C87 "F381A225MMA" 0603S 2459.37,1100.25 r90 top value=2.2uF
C88 "GRM188R61E106MA73D" 0603 1980,1205.14 r90 top value=10uF
C89 "CGA3E1X7R1E105K080AC" 0603S 2145,913.21 r90 top value=1uF
C90 "GRM155R61C104KA88D" 0402 2182.58,1171.42 r0 top value=0.1uF
C91 "C2012X7S2A105K125AB" 0805_HV 1795,1326.03 r180 top value=1uF
C92 "GRM188R61E106MA73D" 0603 2094.19,626.21 r270 top value=10uF
C93 "GRM155R61C104KA88D" 0402 2031.2,619.75 r90 top value=0.1uF
C94 "GRM188R61E106MA73D" 0603 2212.43,722.9 r180 top value=10uF
C95 "GRM155R71C153KA01D" 0402 2243.93,529.48 r180 top value=0.015uF
C96 "GRM155R61C104KA88D" 0402 3588.94,1148.83 r0 top value=0.1uF
C97 "GRM155R72A471KA01D" 0402 5480.92,1496.78 r180 top value=470pF
C98 "GRM155R61C104KA88D" 0402 5270.92,1556.78 r90 top value=0.1uF
C99 "GRM155R61C104KA88D" 0402 5480.92,1721.78 r180 top value=0.1uF
C100 "GRM155R72A471KA01D" 0402 3588.94,1399.93 r0 top value=470pF
C101 "GRM155R72A471KA01D" 0402 5166.06,1528.44 r0 top value=470pF
C102 "GRM155R72A471KA01D" 0402 3759.73,1035.52 r180 top value=470pF
C103 "GRM155R72A471KA01D" 0402 4945.43,1538.12 r180 top value=470pF
C104 "GRM155R61C104KA88D" 0402 4735.43,1548.12 r90 top value=0.1uF
C105 "GRM155R61C104KA88D" 0402 4945.43,1718.12 r180 top value=0.1uF
C106 "GRM155R72A471KA01D" 0402 4119.73,1051.83 r180 top value=470pF
C107 "GRM155R72A471KA01D" 0402 3979.73,1385.52 r180 top value=470pF
C108 "GRM155R72A471KA01D" 0402 4625.43,1583.12 r0 top value=470pF
C109 "GRM155R61C104KA88D" 0402 4422.91,1206.64 r0 top value=0.1uF
C110 "GRM155R61E472KA01D" 0402 4594.37,1090.43 r180 top value=4700pF
C111 "GRM155R61E472KA01D" 0402 4424.69,1433.66 r180 top value=4700pF
C112 "GRM155R61E472KA01D" 0402 4808.87,1422.91 r0 top value=4700pF
C113 "GRM155R61E472KA01D" 0402 4783.35,1090.43 r0 top value=4700pF
C114_1 "GRM155R72A471KA01D" 0402 5799.75,2391.3 r0 top value=470pF (schematic designator C114)
C114_2 "GRM155R72A471KA01D" 0402 4371.75,2395.3 r0 top value=470pF (schematic designator C114)
C114_3 "GRM155R72A471KA01D" 0402 2875.14,2406.91 r0 top value=470pF (schematic designator C114)
C114_4 "GRM155R72A471KA01D" 0402 1451.13,2416.3 r0 top value=470pF (schematic designator C114)
C115_1 "GRM155R61C104KA88D" 0402 5936.65,2307.2 r180 top value=0.1uF (schematic designator C115)
C115_2 "GRM155R61C104KA88D" 0402 4508.65,2311.2 r180 top value=0.1uF (schematic designator C115)
C115_3 "GRM155R61C104KA88D" 0402 3012.05,2322.81 r180 top value=0.1uF (schematic designator C115)
C115_4 "GRM155R61C104KA88D" 0402 1588.03,2332.2 r180 top value=0.1uF (schematic designator C115)
C116 "GRM188R61E106MA73D" 0603 3220,550.14 r270 top value=10uF
C117 "GRM155R61C104KA88D" 0402 2761.57,870.14 r0 top value=0.1uF
C118 "GRM155R61C104KA88D" 0402 2849.09,577.52 r90 top value=0.1uF
C119 "GRM155R61C104KA88D" 0402 2762.59,1026.11 r0 top value=0.1uF
C120 "GRM155R61C104KA88D" 0402 3280.49,1097.29 r180 top value=0.1uF
C121 "GRM155R61C104KA88D" 0402 3165,551.89 r90 top value=0.1uF
C122 "GRM188R61E106MA73D" 0603 2747.91,774.29 r0 top value=10uF
C123 "GRM155R61C104KA88D" 0402 2760,827.03 r0 top value=0.1uF
C124 "GRM155R61C104KA88D" 0402 2768.54,1557.69 r0 top value=0.1uF
C125 "GRM155R61C104KA88D" 0402 2992.01,1113.11 r270 top value=0.1uF
C126 "GRM155R61C104KA88D" 0402 3019.27,566.75 r90 top value=0.1uF
C127 "GRM155R61C104KA88D" 0402 2466.49,1347.69 r0 top value=0.1uF
C128 "GRM155R61C104KA88D" 0402 2703.07,622.94 r180 top value=0.1uF
C129 "GRM155R61C104KA88D" 0402 2948.82,1306.7 r180 top value=0.1uF
C130 "GRM155R61C104KA88D" 0402 3262.61,1522.27 r180 top value=0.1uF
C131 "GRM155R61C104KA88D" 0402 6024.55,1716.19 r0 bottom value=0.1uF
C132 "GRM155R61C104KA88D" 0402 5732.48,1715.14 r0 bottom value=0.1uF
C133 "GRM155R61C104KA88D" 0402 3120.16,1080.14 r0 bottom value=0.1uF
C134 "GRM155R61C104KA88D" 0402 2923.29,1066.83 r180 bottom value=0.1uF
C135 "GRM155R61C104KA88D" 0402 2932.95,560.14 r180 bottom value=0.1uF
C136 "GRM155R61C104KA88D" 0402 3098.43,589.99 r0 bottom value=0.1uF
D1 "150060VS75000" WL-SMCW_GREEN 4170,660.14 r270 top value=Green
D2 "150060VS75000" WL-SMCW_GREEN 2309.1,1425.83 r180 top value=Green
D3 "150060VS75000" WL-SMCW_GREEN 2338.06,580.34 r90 top value=Green
D4_1 "ZHCS350TA" SOD-523 5795.72,2237.28 r0 top value=40V (schematic designator D4)
D4_2 "ZHCS350TA" SOD-523 4367.72,2241.28 r0 top value=40V (schematic designator D4)
D4_3 "ZHCS350TA" SOD-523 2871.11,2252.89 r0 top value=40V (schematic designator D4)
D4_4 "ZHCS350TA" SOD-523 1447.09,2262.28 r0 top value=40V (schematic designator D4)
D5_1 "ZHCS350TA" SOD-523 5799.93,2294.21 r0 top value=40V (schematic designator D5)
D5_2 "ZHCS350TA" SOD-523 4371.93,2298.21 r0 top value=40V (schematic designator D5)
D5_3 "ZHCS350TA" SOD-523 2875.32,2309.82 r0 top value=40V (schematic designator D5)
D5_4 "ZHCS350TA" SOD-523 1451.31,2319.21 r0 top value=40V (schematic designator D5)
D6 "LTST-C170KRKT" LED_LTST-C170_Red 3450.84,818.11 r90 top value=Red
D7 "LTST-C171TBKT" LTST-C171_Blue 3421.59,982.92 r90 top value=Blue
F1_1 "CB61F15A-TR1" 6125FA 5046.37,1967.05 r270 top (schematic designator F1)
F1_2 "CB61F15A-TR1" 6125FA 3618.37,1971.05 r270 top (schematic designator F1)
F1_3 "CB61F15A-TR1" 6125FA 2121.76,1982.66 r270 top (schematic designator F1)
F1_4 "CB61F15A-TR1" 6125FA 705,1980.14 r270 top (schematic designator F1)
FID1 "Fiducial" Fiducial10-20 206.66,1920.14 r0 top
FID2 "Fiducial" Fiducial10-20 6312.39,4896.67 r0 top
FID3 "Fiducial" Fiducial10-20 6310,4160.14 r0 top
H1 "NY PMS 440 0025 PH" "NY PMS 440 0025 PH" 195,5600.14 r0 top
H2 "NY PMS 440 0025 PH" "NY PMS 440 0025 PH" 6240,5600.14 r0 top
H3 "NY PMS 440 0025 PH" "NY PMS 440 0025 PH" 6255,205.14 r0 top
H4 "NY PMS 440 0025 PH" "NY PMS 440 0025 PH" 190.98,187.66 r0 top
H5 "1902C" Keystone_1902C 6255,205.14 r180 bottom
H6 "1902C" Keystone_1902C 6240,5600.14 r180 bottom
H7 "1902C" Keystone_1902C 180,180.14 r180 bottom
H8 "1902C" Keystone_1902C 195,5600.14 r180 bottom
J1 "108-0740-001" Johnson_108-0740-001 504.06,1350.14 r0 top
J2 "108-0740-001" Johnson_108-0740-001 527.83,646.99 r0 top
J3 "B2B-EH-A(LF)(SN)" JST_B2B-EH-A 6313.42,853.01 r90 top
J6 "HTSW-103-07-G-S" Samtec_HTSW-103-07-G-S 6310,2898.95 r270 top
J7_1 "108-0740-001" Johnson_108-0740-001 5020,5329.03 r270 top (schematic designator J7)
J7_2 "108-0740-001" Johnson_108-0740-001 3596.97,5320.71 r270 top (schematic designator J7)
J7_3 "108-0740-001" Johnson_108-0740-001 2095.39,5322.32 r270 top (schematic designator J7)
J7_4 "108-0740-001" Johnson_108-0740-001 695,5323.65 r270 top (schematic designator J7)
J8_1 "108-0740-001" Johnson_108-0740-001 5783.43,5319.35 r270 top (schematic designator J8)
J8_2 "108-0740-001" Johnson_108-0740-001 4362,5318.35 r270 top (schematic designator J8)
J8_3 "108-0740-001" Johnson_108-0740-001 2860.39,5319.95 r270 top (schematic designator J8)
J8_4 "108-0740-001" Johnson_108-0740-001 1460,5321.28 r270 top (schematic designator J8)
J9_1 "HTSW-102-07-G-S" Samtec_HTSW-102-07-G-S 5701.4,4145.34 r270 top (schematic designator J9)
J9_2 "HTSW-102-07-G-S" Samtec_HTSW-102-07-G-S 4269.49,4155.29 r270 top (schematic designator J9)
J9_3 "HTSW-102-07-G-S" Samtec_HTSW-102-07-G-S 2768.48,4154.39 r270 top (schematic designator J9)
J9_4 "HTSW-102-07-G-S" Samtec_HTSW-102-07-G-S 1378.99,4160.94 r270 top (schematic designator J9)
J10_1 "B2B-EH-A(LF)(SN)" JST_B2B-EH-A 5542.95,4754.25 r180 top (schematic designator J10)
J10_2 "B2B-EH-A(LF)(SN)" JST_B2B-EH-A 4111.71,4754.14 r180 top (schematic designator J10)
J10_3 "B2B-EH-A(LF)(SN)" JST_B2B-EH-A 2619.28,4765.75 r180 top (schematic designator J10)
J10_4 "B2B-EH-A(LF)(SN)" JST_B2B-EH-A 1217.22,4779.25 r180 top (schematic designator J10)
J11 "HSEC8-160-01-L-DV-A-BL" controlCARD-120HSEC 4794.69,274.08 r180 top
J12 "HSEC8-130-01-L-DV-A" controlCARD-180HSEC-60pinAddon 2446.69,274.08 r180 top
J14 "HTSW-102-07-G-S" Samtec_HTSW-102-07-G-S 1787.64,254.71 r90 top
J15 "HTSW-102-07-G-S" Samtec_HTSW-102-07-G-S 1740,1050.25 r0 top
J16 "HTSW-103-07-G-S" Samtec_HTSW-103-07-G-S 534.88,257.98 r180 top
J17 "HTSW-102-07-G-S" Samtec_HTSW-102-07-G-S 1971.46,1050.23 r180 top
L1_1 "XAL1580-102MEB" XAL1580 5201.22,3129.44 r90 top value=1uH (schematic designator L1)
L1_2 "XAL1580-102MEB" XAL1580 3773.22,3133.44 r90 top value=1uH (schematic designator L1)
L1_3 "XAL1580-102MEB" XAL1580 2276.61,3145.05 r90 top value=1uH (schematic designator L1)
L1_4 "XAL1580-102MEB" XAL1580 852.59,3154.44 r90 top value=1uH (schematic designator L1)
L2 "XGL6060-223MEC" FP-XGL6060-223MEC_SMT2_6MM51_6MM71-MFG 1451.48,285.14 r0 top value=22uH
L3 "XGL6060-223MEC" FP-XGL6060-223MEC_SMT2_6MM51_6MM71-MFG 1614.36,640.37 r0 top value=22uH
L4 "BLM41PG102SN1L" 1806_HighSpeed 1949.31,874.73 r270 top value="1000 ohm"
LBL1 "THT-14-423-10" Label_650x200 5024.57,1031.1 r180 bottom
Logo1 "CE Mark" CE_Mark_5mm 5995.87,975.84 r180 bottom
Logo2 "Texas Instruments" TI_Stacked_Overlay_Small 5739.21,1271.42 r180 bottom
Logo3 "FCC disclaimer" FCC_disclaimer 5493.78,435 r180 bottom
Logo4 "WEEE logo" WEEE_Minimum 5696.45,1014.51 r180 bottom
Logo5 "CAUTION HOT SURFACE" IEC_HotSurface_Large 3638,3190.14 r180 bottom
Logo6 "CAUTION HOT SURFACE" IEC_HotSurface_Large 708,3190.14 r180 bottom
Logo7 "CAUTION HOT SURFACE" IEC_HotSurface_Large 5110,3190.14 r180 bottom
Logo8 "CAUTION HOT SURFACE" IEC_HotSurface_Large 2170,3190.14 r180 bottom
NT1_1 "Net-Tie" Net-Tie_10mil 5588.05,2344.53 r270 top net-tie (schematic designator NT1)
NT1_2 "Net-Tie" Net-Tie_10mil 4151.15,2337.34 r0 top net-tie (schematic designator NT1)
NT1_3 "Net-Tie" Net-Tie_10mil 2663.44,2360.14 r270 top net-tie (schematic designator NT1)
NT1_4 "Net-Tie" Net-Tie_10mil 1233.33,2358.23 r0 top net-tie (schematic designator NT1)
NT2_1 "Net-Tie" Net-Tie_10mil 5651.4,2698.35 r90 top net-tie (schematic designator NT2)
NT2_2 "Net-Tie" Net-Tie_10mil 4223.4,2702.35 r90 top net-tie (schematic designator NT2)
NT2_3 "Net-Tie" Net-Tie_10mil 2726.79,2703.95 r90 top net-tie (schematic designator NT2)
NT2_4 "Net-Tie" Net-Tie_10mil 1302.77,2723.35 r90 top net-tie (schematic designator NT2)
Q1_1 "CSD16570Q5B" DNK0008A 4919,4416.47 r270 top value=25V (schematic designator Q1)
Q1_2 "CSD16570Q5B" DNK0008A 3491,4420.47 r270 top value=25V (schematic designator Q1)
Q1_3 "CSD16570Q5B" DNK0008A 1994.39,4432.08 r270 top value=25V (schematic designator Q1)
Q1_4 "CSD16570Q5B" DNK0008A 594,4443.41 r270 top value=25V (schematic designator Q1)
Q2_1 "CSD16570Q5B" DNK0008A 4919,4723.55 r90 top value=25V (schematic designator Q2)
Q2_2 "CSD16570Q5B" DNK0008A 3491,4727.55 r90 top value=25V (schematic designator Q2)
Q2_3 "CSD16570Q5B" DNK0008A 1994.39,4739.16 r90 top value=25V (schematic designator Q2)
Q2_4 "CSD16570Q5B" DNK0008A 594,4750.49 r90 top value=25V (schematic designator Q2)
Q3_1 "CSD16570Q5B" DNK0008A 5257.36,4415.47 r270 top value=25V (schematic designator Q3)
Q3_2 "CSD16570Q5B" DNK0008A 3829.36,4419.47 r270 top value=25V (schematic designator Q3)
Q3_3 "CSD16570Q5B" DNK0008A 2332.75,4431.08 r270 top value=25V (schematic designator Q3)
Q3_4 "CSD16570Q5B" DNK0008A 932.36,4442.41 r270 top value=25V (schematic designator Q3)
Q4_1 "CSD16570Q5B" DNK0008A 5257.36,4722.55 r90 top value=25V (schematic designator Q4)
Q4_2 "CSD16570Q5B" DNK0008A 3829.36,4726.55 r90 top value=25V (schematic designator Q4)
Q4_3 "CSD16570Q5B" DNK0008A 2332.75,4738.16 r90 top value=25V (schematic designator Q4)
Q4_4 "CSD16570Q5B" DNK0008A 932.36,4749.49 r90 top value=25V (schematic designator Q4)
Q5 "2N7002-7-F" SOT-23 3330,556.52 r90 top value=60V
R1_1 "CRCW04023R01FNED" FP-CRCW0402-e3-MFG 5396.5,2320.02 r180 top (schematic designator R1)
R1_2 "CRCW04023R01FNED" FP-CRCW0402-e3-MFG 3967,2327.16 r180 top (schematic designator R1)
R1_3 "CRCW04023R01FNED" FP-CRCW0402-e3-MFG 2470.39,2336.64 r180 top (schematic designator R1)
R1_4 "CRCW04023R01FNED" FP-CRCW0402-e3-MFG 1049.77,2348.06 r180 top (schematic designator R1)
R2_1 "BVB-Z-R0005-1.0" FP-WSLP2726L5000FEA_2726-MFG 5058,4058.16 r270 top (schematic designator R2)
R2_2 "BVB-Z-R0005-1.0" FP-WSLP2726L5000FEA_2726-MFG 3624.44,4055.06 r270 top (schematic designator R2)
R2_3 "BVB-Z-R0005-1.0" FP-WSLP2726L5000FEA_2726-MFG 2115.39,4068.46 r270 top (schematic designator R2)
R2_4 "BVB-Z-R0005-1.0" FP-WSLP2726L5000FEA_2726-MFG 703.82,4076.06 r270 top (schematic designator R2)
R3_1 "CRCW080510R0JNEA" 0805_HV 4893.62,2665.08 r0 top value=10 (schematic designator R3)
R3_2 "CRCW080510R0JNEA" 0805_HV 3465.62,2669.08 r0 top value=10 (schematic designator R3)
R3_3 "CRCW080510R0JNEA" 0805_HV 1969.01,2680.68 r0 top value=10 (schematic designator R3)
R3_4 "CRCW080510R0JNEA" 0805_HV 545,2690.08 r0 top value=10 (schematic designator R3)
R4_1 "CSR0402FK1R00" 0402 5263.54,4032.84 r180 top value=1.00 (schematic designator R4)
R4_2 "CSR0402FK1R00" 0402 3835.54,4036.84 r180 top value=1.00 (schematic designator R4)
R4_3 "CSR0402FK1R00" 0402 2338.93,4048.45 r180 top value=1.00 (schematic designator R4)
R4_4 "CSR0402FK1R00" 0402 914.91,4057.84 r180 top value=1.00 (schematic designator R4)
R5_1 "CSR0402FK1R00" 0402 5263.54,4082.84 r180 top value=1.00 (schematic designator R5)
R5_2 "CSR0402FK1R00" 0402 3835.54,4086.84 r180 top value=1.00 (schematic designator R5)
R5_3 "CSR0402FK1R00" 0402 2338.93,4098.45 r180 top value=1.00 (schematic designator R5)
R5_4 "CSR0402FK1R00" 0402 914.91,4107.84 r180 top value=1.00 (schematic designator R5)
R6_1 "CRCW08051K00FKEA" 0805_HV 5298.39,4232.12 r180 top value=1.00k (schematic designator R6)
R6_2 "CRCW08051K00FKEA" 0805_HV 3870,4238.05 r180 top value=1.00k (schematic designator R6)
R6_3 "CRCW08051K00FKEA" 0805_HV 2383.47,4245.1 r180 top value=1.00k (schematic designator R6)
R6_4 "CRCW08051K00FKEA" 0805_HV 974.6,4255.82 r180 top value=1.00k (schematic designator R6)
R7_1 "CRCW08051K00FKEA" 0805_HV 5527.99,3777.18 r180 top value=1.00k (schematic designator R7)
R7_2 "CRCW08051K00FKEA" 0805_HV 4093.1,3786.35 r180 top value=1.00k (schematic designator R7)
R7_3 "CRCW08051K00FKEA" 0805_HV 2598.93,3794.69 r180 top value=1.00k (schematic designator R7)
R7_4 "CRCW08051K00FKEA" 0805_HV 1190,3807.53 r180 top value=1.00k (schematic designator R7)
R8 "CRCW04020000Z0ED" 0402 4554.67,1590.17 r270 bottom value=0
R9_1 "CRCW04023R01FNED" FP-CRCW0402-e3-MFG 5688.58,2317.64 r180 top (schematic designator R9)
R9_2 "CRCW04023R01FNED" FP-CRCW0402-e3-MFG 4260.58,2321.64 r180 top (schematic designator R9)
R9_3 "CRCW04023R01FNED" FP-CRCW0402-e3-MFG 2763.98,2333.25 r180 top (schematic designator R9)
R9_4 "CRCW04023R01FNED" FP-CRCW0402-e3-MFG 1339.96,2342.64 r180 top (schematic designator R9)
R10_1 "PCF0402-12-10K0BT1" 0402 6033.46,2242.4 r270 top value=10.0k (schematic designator R10)
R10_2 "PCF0402-12-10K0BT1" 0402 4612.28,2241.28 r270 top value=10.0k (schematic designator R10)
R10_3 "PCF0402-12-10K0BT1" 0402 3115.67,2252.89 r270 top value=10.0k (schematic designator R10)
R10_4 "PCF0402-12-10K0BT1" 0402 1691.65,2262.28 r270 top value=10.0k (schematic designator R10)
R11_1 "PCF0402-12-10K0BT1" 0402 5567.16,2177.33 r270 top value=10.0k (schematic designator R11)
R11_2 "PCF0402-12-10K0BT1" 0402 4139.16,2181.33 r270 top value=10.0k (schematic designator R11)
R11_3 "PCF0402-12-10K0BT1" 0402 2642.55,2192.94 r270 top value=10.0k (schematic designator R11)
R11_4 "PCF0402-12-10K0BT1" 0402 1218.54,2202.33 r270 top value=10.0k (schematic designator R11)
R12_1 "PCF0402-12-10K0BT1" 0402 5252.12,3961.14 r270 top value=10.0k (schematic designator R12)
R12_2 "PCF0402-12-10K0BT1" 0402 3824.12,3965.14 r270 top value=10.0k (schematic designator R12)
R12_3 "PCF0402-12-10K0BT1" 0402 2327.51,3976.75 r270 top value=10.0k (schematic designator R12)
R12_4 "PCF0402-12-10K0BT1" 0402 903.5,3986.14 r270 top value=10.0k (schematic designator R12)
R13_1 "PCF0402-12-10K0BT1" 0402 5298,3961.14 r270 top value=10.0k (schematic designator R13)
R13_2 "PCF0402-12-10K0BT1" 0402 3870,3965.14 r270 top value=10.0k (schematic designator R13)
R13_3 "PCF0402-12-10K0BT1" 0402 2373.39,3976.75 r270 top value=10.0k (schematic designator R13)
R13_4 "PCF0402-12-10K0BT1" 0402 949.38,3986.14 r270 top value=10.0k (schematic designator R13)
R14_1 "CRCW04023R01FNED" FP-CRCW0402-e3-IPC_C 5647.39,2766.46 r0 top (schematic designator R14)
R14_2 "CRCW04023R01FNED" FP-CRCW0402-e3-IPC_C 4222.13,2790.14 r0 top (schematic designator R14)
R14_3 "CRCW04023R01FNED" FP-CRCW0402-e3-IPC_C 2723.83,2780.14 r0 top (schematic designator R14)
R14_4 "CRCW04023R01FNED" FP-CRCW0402-e3-IPC_C 1301.17,2810.14 r0 top (schematic designator R14)
R15_1 "CRCW04020000Z0ED" 0402 5794.48,2188.29 r180 top value=0 (schematic designator R15)
R15_2 "CRCW04020000Z0ED" 0402 4366.48,2192.29 r180 top value=0 (schematic designator R15)
R15_3 "CRCW04020000Z0ED" 0402 2869.87,2203.89 r180 top value=0 (schematic designator R15)
R15_4 "CRCW04020000Z0ED" 0402 1445.85,2213.29 r180 top value=0 (schematic designator R15)
R16 "CRCW04020000Z0ED" 0402 6167.06,1602.65 r270 top value=0
R17_1 "CSR0402FK1R00" 0402 5491.26,4611.53 r90 top value=1.00 (schematic designator R17)
R17_2 "CSR0402FK1R00" 0402 4060.56,4615.53 r90 top value=1.00 (schematic designator R17)
R17_3 "CSR0402FK1R00" 0402 2566.65,4624.98 r90 top value=1.00 (schematic designator R17)
R17_4 "CSR0402FK1R00" 0402 1166.38,4638.47 r90 top value=1.00 (schematic designator R17)
R18_1 "CSR0402FK1R00" 0402 5591.26,4610.37 r270 top value=1.00 (schematic designator R18)
R18_2 "CSR0402FK1R00" 0402 4163.26,4614.37 r270 top value=1.00 (schematic designator R18)
R18_3 "CSR0402FK1R00" 0402 2666.65,4625.98 r270 top value=1.00 (schematic designator R18)
R18_4 "CSR0402FK1R00" 0402 1266.26,4637.31 r270 top value=1.00 (schematic designator R18)
R19_1 "CRCW04020000Z0ED" 0402 5434.69,4906.49 r270 top value=0 (schematic designator R19)
R19_2 "CRCW04020000Z0ED" 0402 4006.69,4910.49 r270 top value=0 (schematic designator R19)
R19_3 "CRCW04020000Z0ED" 0402 2510.08,4922.1 r270 top value=0 (schematic designator R19)
R19_4 "CRCW04020000Z0ED" 0402 1109.69,4933.43 r270 top value=0 (schematic designator R19)
R20_1 "CSR0402FK1R00" 0402 5443.39,4611.53 r90 top value=1.00 (schematic designator R20)
R20_2 "CSR0402FK1R00" 0402 4006.69,4615.53 r90 top value=1.00 (schematic designator R20)
R20_3 "CSR0402FK1R00" 0402 2514.01,4624.98 r90 top value=1.00 (schematic designator R20)
R20_4 "CSR0402FK1R00" 0402 1118.39,4638.47 r90 top value=1.00 (schematic designator R20)
R21_1 "CSR0402FK1R00" 0402 5541.26,4610.37 r270 top value=1.00 (schematic designator R21)
R21_2 "CSR0402FK1R00" 0402 4113.26,4614.37 r270 top value=1.00 (schematic designator R21)
R21_3 "CSR0402FK1R00" 0402 2616.65,4625.98 r270 top value=1.00 (schematic designator R21)
R21_4 "CSR0402FK1R00" 0402 1216.26,4637.31 r270 top value=1.00 (schematic designator R21)
R22_1 "CRCW04020000Z0ED" 0402 5484.69,4905.11 r270 top value=0 (schematic designator R22)
R22_2 "CRCW04020000Z0ED" 0402 4058.59,4908.36 r270 top value=0 (schematic designator R22)
R22_3 "CRCW04020000Z0ED" 0402 2563.95,4919.97 r270 top value=0 (schematic designator R22)
R22_4 "CRCW04020000Z0ED" 0402 1171.42,4933.46 r270 top value=0 (schematic designator R22)
R23_1 "PCF0402-12-10K0BT1" 0402 5551.1,3869.5 r0 top value=10.0k (schematic designator R23)
R23_2 "PCF0402-12-10K0BT1" 0402 4123.1,3873.5 r0 top value=10.0k (schematic designator R23)
R23_3 "PCF0402-12-10K0BT1" 0402 2626.49,3885.11 r0 top value=10.0k (schematic designator R23)
R23_4 "PCF0402-12-10K0BT1" 0402 1226.1,3896.44 r0 top value=10.0k (schematic designator R23)
R24_1 "PCF0402-12-10K0BT1" 0402 5955.6,2035.14 r180 top value=10.0k (schematic designator R24)
R24_2 "PCF0402-12-10K0BT1" 0402 4527.6,2039.14 r180 top value=10.0k (schematic designator R24)
R24_3 "PCF0402-12-10K0BT1" 0402 3031,2050.75 r180 top value=10.0k (schematic designator R24)
R24_4 "PCF0402-12-10K0BT1" 0402 1611.65,2061.89 r180 top value=10.0k (schematic designator R24)
R25_1 "CRCW040210R0FKED" 0402 5462.24,4528.88 r0 top value=10.0 (schematic designator R25)
R25_2 "CRCW040210R0FKED" 0402 4034.24,4532.88 r0 top value=10.0 (schematic designator R25)
R25_3 "CRCW040210R0FKED" 0402 2537.64,4544.48 r0 top value=10.0 (schematic designator R25)
R25_4 "CRCW040210R0FKED" 0402 1137.24,4555.81 r0 top value=10.0 (schematic designator R25)
R26_1 "CRCW040212K4FKED" 0402 5784.65,1880.14 r0 top value=12.4k (schematic designator R26)
R26_2 "CRCW040212K4FKED" 0402 4356.65,1884.14 r0 top value=12.4k (schematic designator R26)
R26_3 "CRCW040212K4FKED" 0402 2860.04,1895.75 r0 top value=12.4k (schematic designator R26)
R26_4 "CRCW040212K4FKED" 0402 1445,1910.14 r0 top value=12.4k (schematic designator R26)
R27_1 "RC1005F104CS" 0402 5956.61,1985.14 r180 top value=100k (schematic designator R27)
R27_2 "RC1005F104CS" 0402 4528.61,1989.14 r180 top value=100k (schematic designator R27)
R27_3 "RC1005F104CS" 0402 3032,2000.75 r180 top value=100k (schematic designator R27)
R27_4 "RC1005F104CS" 0402 1611.65,2015.14 r180 top value=100k (schematic designator R27)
